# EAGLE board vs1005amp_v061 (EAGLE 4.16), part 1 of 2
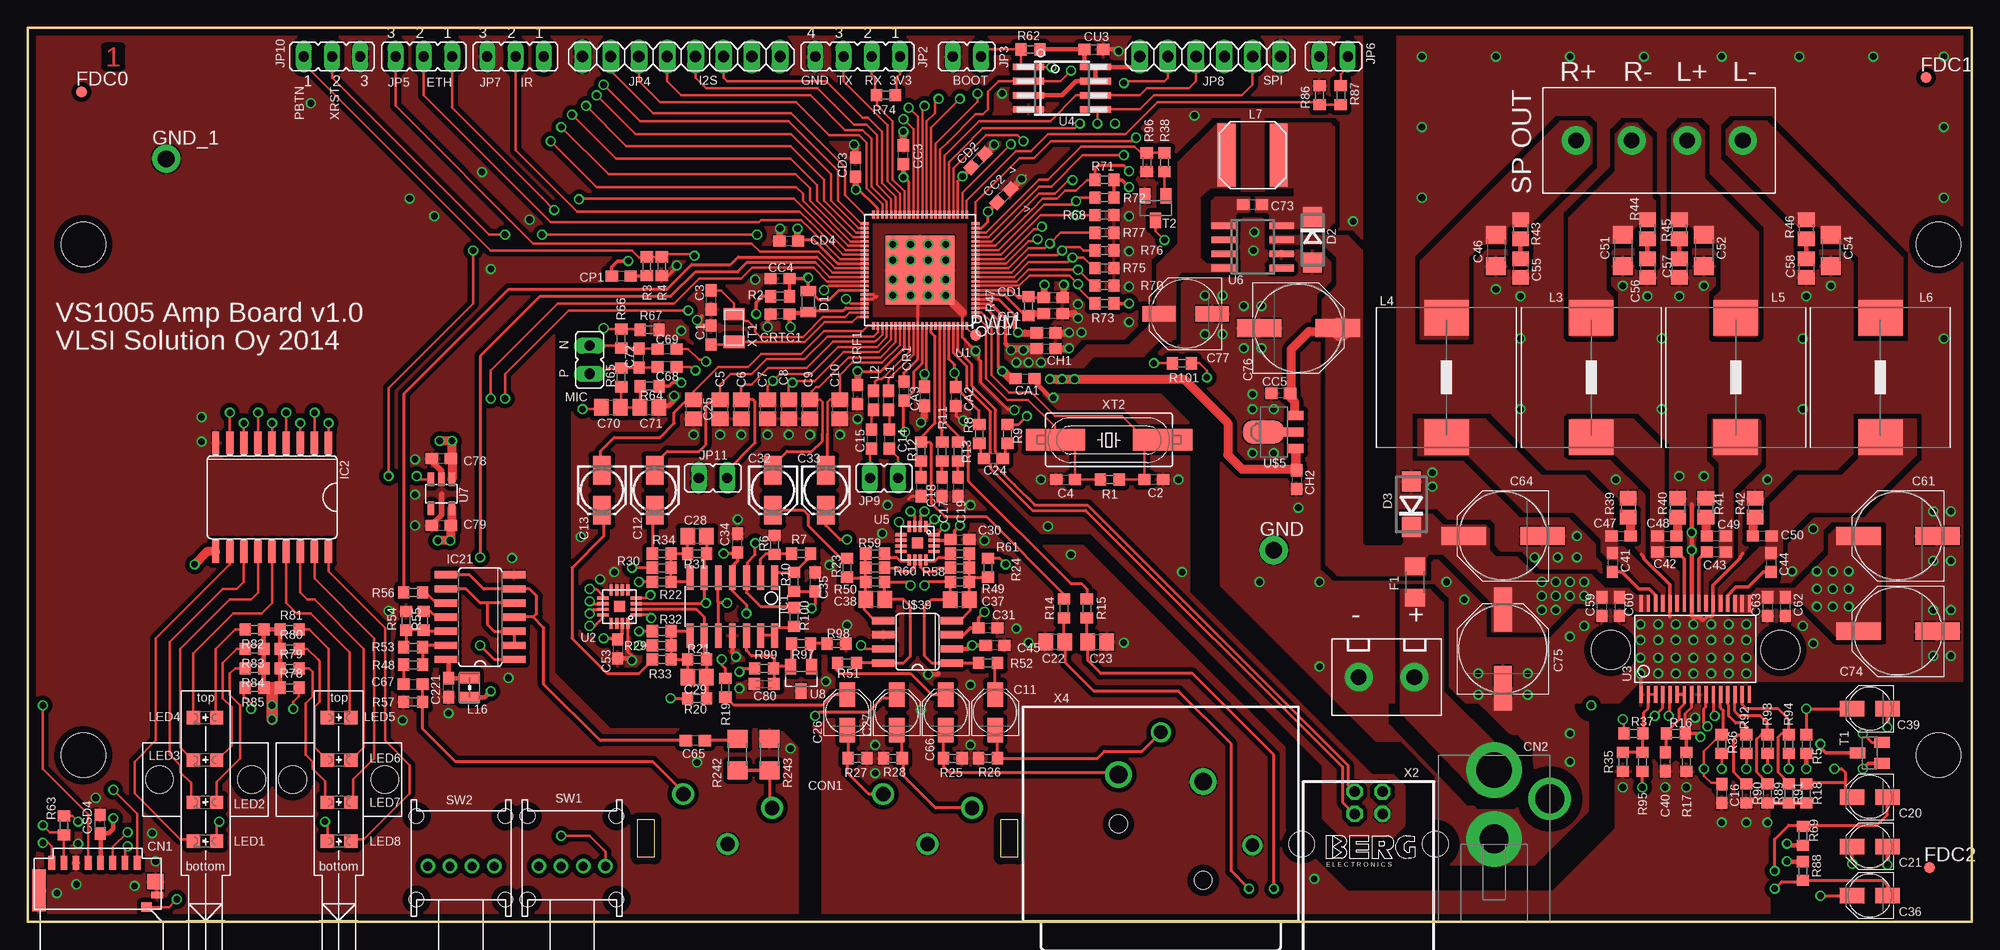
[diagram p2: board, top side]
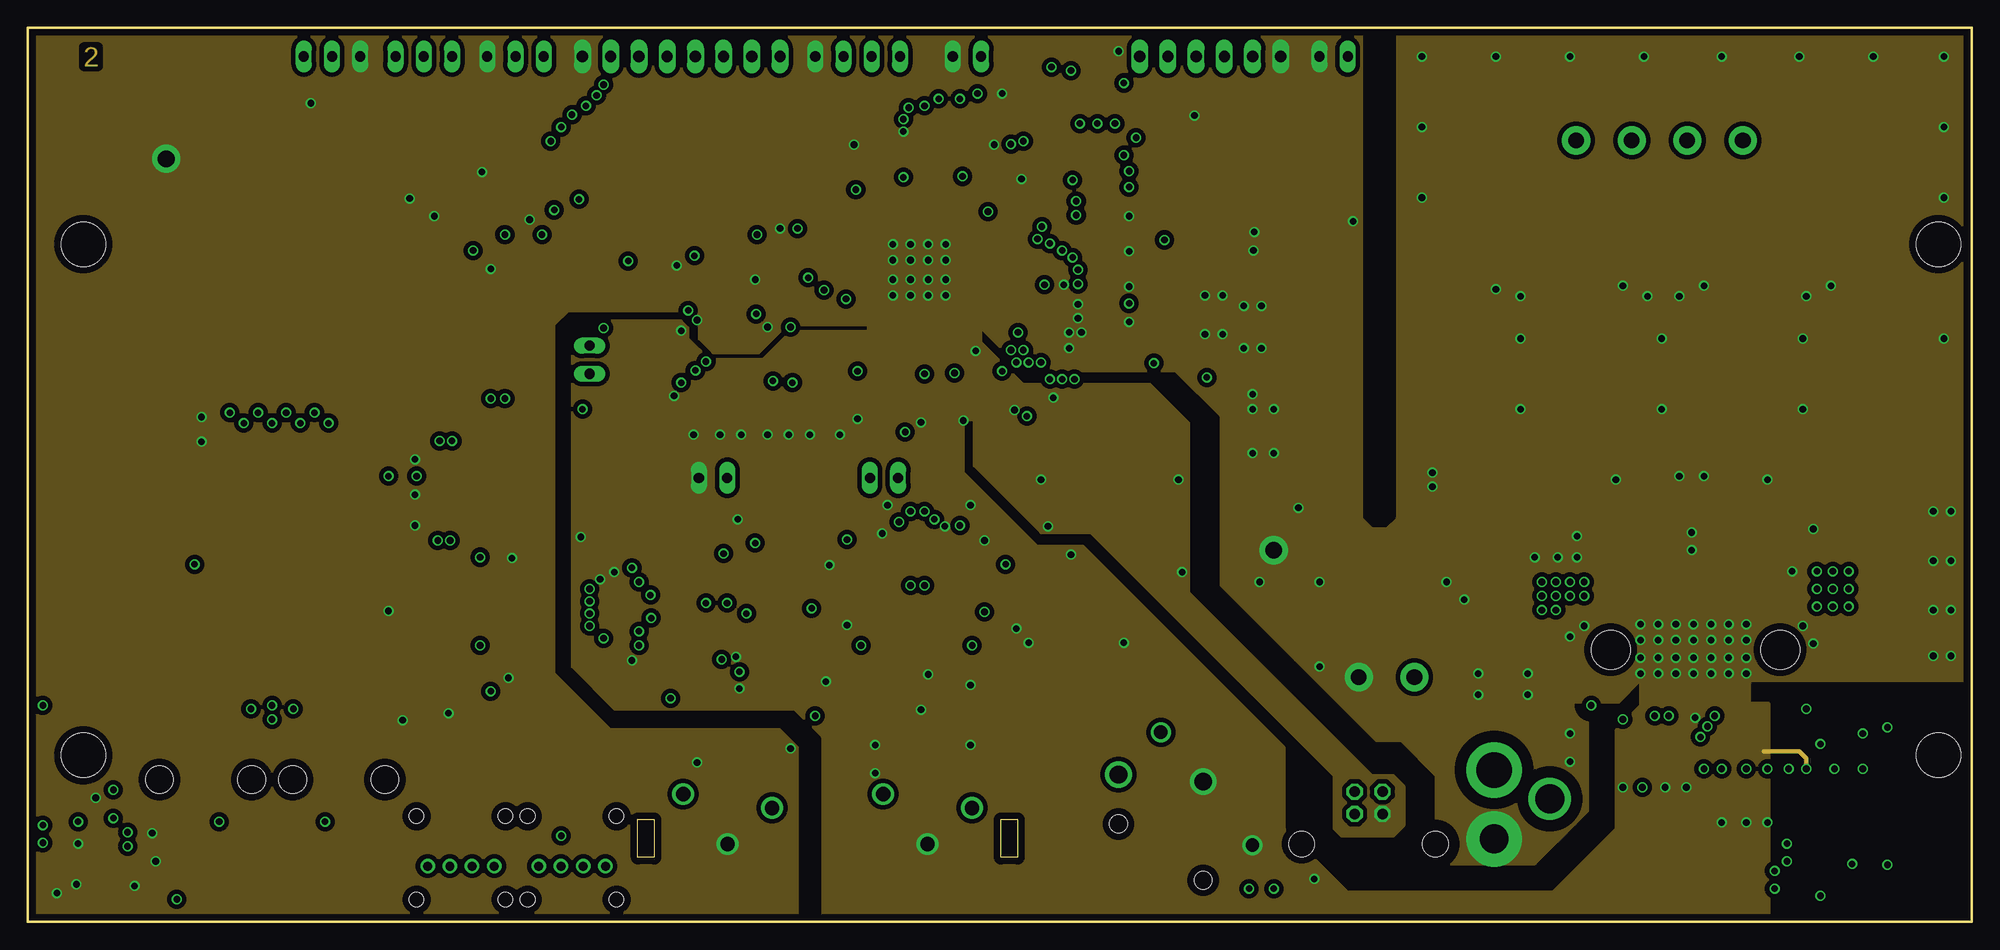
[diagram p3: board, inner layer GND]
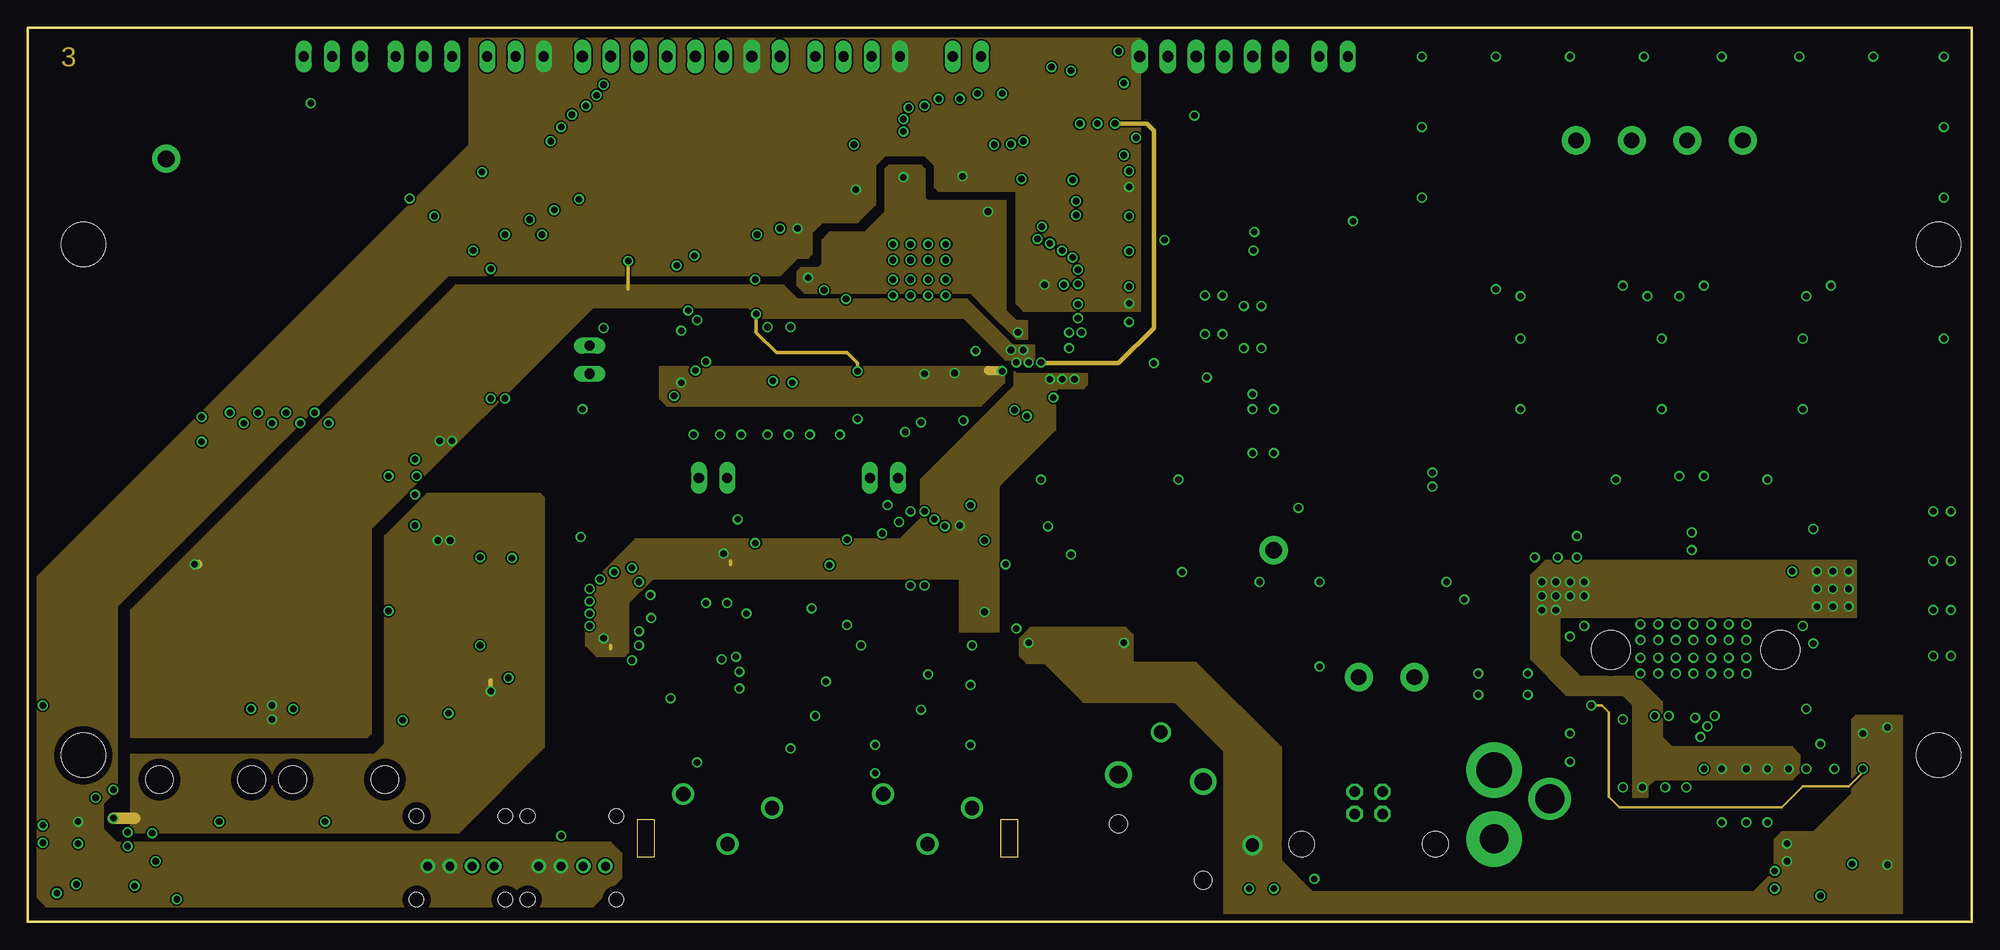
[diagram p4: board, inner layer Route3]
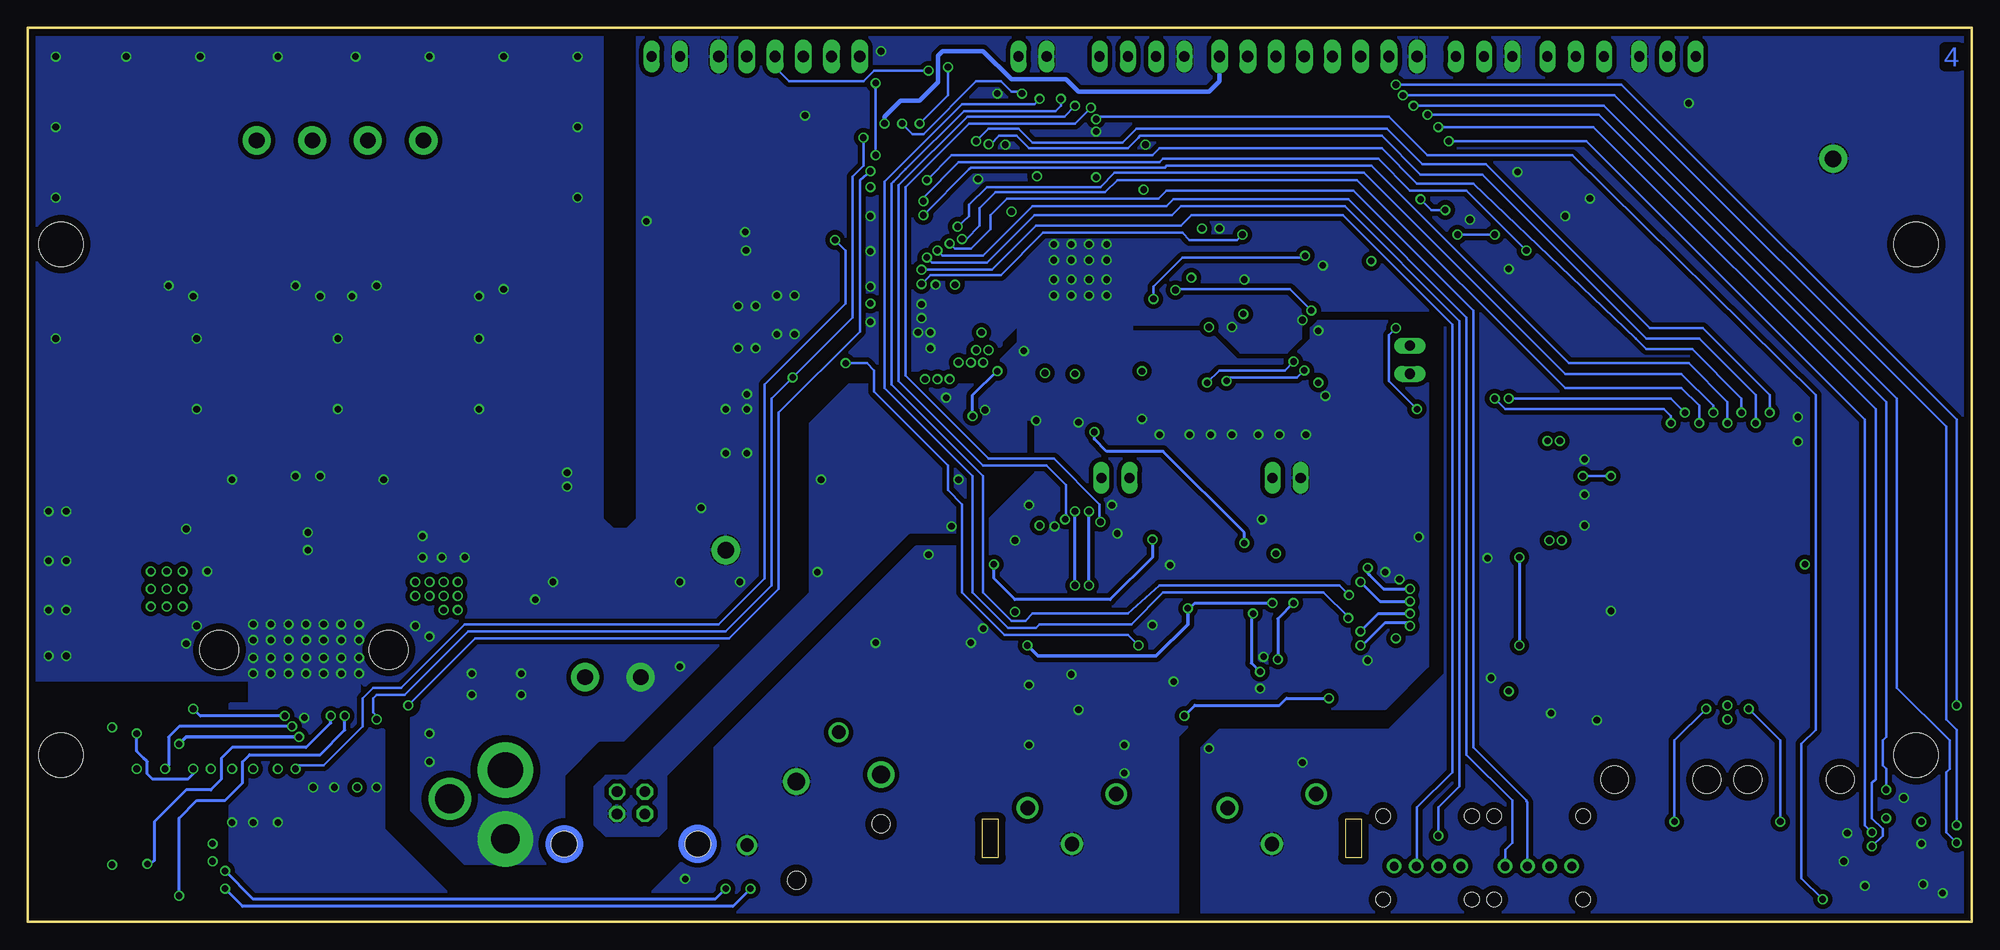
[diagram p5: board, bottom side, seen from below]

Size 175 x 80.5 mm. Coordinates in mm from the lower left corner, seen from the top.
Outline: 0,0 175,0 175,80.5 0,80.5 0,0
Copper layers (1*2+3*16): Top 0.0356mm / dielectric 0.2007mm / GND 0.0356mm / dielectric 0.2007mm / Route3 0.0356mm / dielectric 0.2007mm / Bottom 0.0356mm
Design rules "oma_4layer": minimum track width 8mil, minimum drill 0.3mm, track to track 5.5mil, track to pad 5.5mil, pad to pad 5.5mil, via to via 8mil, smd to smd 5mil, copper to edge 24mil, drill to drill 8mil, minimum pad ring 10mil, minimum via ring 0.15mm, stop-mask expansion 0.1mm, vias tented up to drill 100mil, thermal gap 5mil
Holes 4 mm at 172,15 5,15 172,61 5,61
Holes 3.5 mm at 157.75,24.5 142.5,24.5

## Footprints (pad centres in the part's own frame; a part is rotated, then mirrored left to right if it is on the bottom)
C0603 = smd 1.1 x 1: 1 -0.85,0; 2 0.85,0
C0805 = smd 1.3 x 1.5: 1 -0.85,0; 2 0.85,0
PANASONIC_B = smd 2.2 x 1.4: + 1.6,0; - -1.6,0
153CLV-0405 = smd 2.6 x 1.6: + 1.8,0; - -1.8,0
C1206 = smd 1.6 x 1.8: 1 -1.4,0; 2 1.4,0
PANASONIC_F = smd 4 x 1.6: + 3.55,0; - -3.55,0
PANASONIC_D = smd 3 x 1.4: + 2.4,0; - -2.4,0
C0603K = smd 1.05 x 1.08: 1 -0.875,0; 2 0.875,0
MSSN09-A0-300 = smd 0.6 x 1.25: 1 3.85,0; 2 2.75,0; 3 1.65,0; 4 0.55,0; 5 -0.55,0; 6 -1.65,0; 7 -2.75,0; 8 -3.85,0 | smd 1.2 x 3.79: 9 -5,-2.5 | smd 1.45 x 1.4: 10 5.5,-1.7 | smd 1.1 x 0.6: 11 5.65,-2.9 | smd 0.95 x 0.85: 12 4.7,-4
DC-JACK = drill 3.2 pad 5 round: 1 -13.7,0 | drill 2.6 pad 3.81 round: 2 -11.1,5 | drill 2.6 pad 5 round: 3 -7.5,0
LIGHT_PIPE4 = hole 2.5: -4.15,0; 4.15,0
4XRCA_2X2 = drill 1.3 round: GL 9,0; GR -9,0; RL 5,-3.25; RR -13,-3.25; WL 13,-4.5; WR -5,-4.5
MICROMELF-W = smd 0.9 x 1.4: A 0.95,0; C -0.95,0
DO214AC = smd 1.8 x 1.7: A 2.05,0; C -2.05,0
DO214BA = smd 1.8 x 1.7: A 2.05,0; C -2.05,0
R1206 = smd 1.6 x 1.803: 1 -1.422,0; 2 1.422,0
TP10R = smd 1 x 1: TP 0,0
MEAS_PIN = drill 1.5 pad 2.54 round: P$1 0,0
SO14 = smd 0.61 x 2.21: 1 -3.81,-2.603; 2 -2.54,-2.603; 3 -1.27,-2.603; 4 0,-2.603; 5 1.27,-2.603; 6 2.54,-2.603; 7 3.81,-2.603; 8 3.81,2.603; 9 2.54,2.603; 10 1.27,2.603; 11 0,2.603; 12 -1.27,2.603; 13 -2.54,2.603; 14 -3.81,2.603
SO18L = smd 0.66 x 2.032: 1 -5.08,-4.902; 2 -3.81,-4.902; 3 -2.54,-4.902; 4 -1.27,-4.902; 5 0,-4.902; 6 1.27,-4.902; 7 2.54,-4.902; 8 3.81,-4.902; 9 5.08,-4.902; 10 5.08,4.902; 11 3.81,4.902; 12 2.54,4.902; 13 1.27,4.902; 14 0,4.902; 15 -1.27,4.902; 16 -2.54,4.902; 17 -3.81,4.902; 18 -5.08,4.902
SO14' = smd 0.66 x 2.032: 1 -3.81,-3.073; 2 -2.54,-3.073; 3 -1.27,-3.073; 4 0,-3.073; 5 1.27,-3.073; 6 2.54,-3.073; 7 3.81,-3.073; 8 3.81,3.073; 9 2.54,3.073; 10 1.27,3.073; 11 0,3.073; 12 -1.27,3.073; 13 -2.54,3.073; 14 -3.81,3.073
JP4 = drill 0.914 long: 1 -3.81,0; 2 -1.27,0; 3 1.27,0; 4 3.81,0
JP1 = drill 0.914 long: 1 0,-1.27; 2 0,1.27
1X08 = drill 1.016 long: 1 -8.89,0; 2 -6.35,0; 3 -3.81,0; 4 -1.27,0; 5 1.27,0; 6 3.81,0; 7 6.35,0; 8 8.89,0
JP2 = drill 0.914 long: 1 -2.54,0; 2 0,0; 3 2.54,0
1X06 = drill 1.016 long: 1 -6.35,0; 2 -3.81,0; 3 -1.27,0; 4 1.27,0; 5 3.81,0; 6 6.35,0
0603 = smd 1.1 x 1: 1 -0.85,0; 2 0.85,0
RLF12560 = smd 3.2 x 4: 1 -5.375,0; 2 5.375,0
L_NR6045 = smd 1.6 x 5.7: 1 -2.35,0; 2 2.35,0
WE-KI_0805_B = smd 1.02 x 1.78: 1 -0.89,0; 2 0.89,0
CHIPLED_0805 = smd 1.2 x 1.2: A 0,-1.05; C 0,1.05
R0603 = smd 1 x 1.1: 1 -0.85,0; 2 0.85,0
R0805 = smd 1.3 x 1.5: 1 -0.85,0; 2 0.85,0
SW_MJTP2205D = drill 0.8 round: 1 3,0; 2 1,0; 3 -1,0; 4 -3,0 | hole 1.3: 4,-3; -4,-3; 4,4.5; -4,4.5
SOT23 = smd 1 x 1.4: 1 -0.95,-1.1; 2 0.95,-1.1; 3 0,1.1
QFN88_2 = smd 0.25 x 0.7: 1 0.8,0; 2 1.2,0; 3 1.6,0; 4 2,0; 5 2.4,0; 6 2.8,0; 7 3.2,0; 8 3.6,0; 9 4,0; 10 4.4,0; 11 4.8,0; 12 5.2,0; 13 5.6,0; 14 6,0; 15 6.4,0; 16 6.8,0; 17 7.2,0; 18 7.6,0; 19 8,0; 20 8.4,0; 21 8.8,0; 22 9.2,0; 45 9.2,10; 46 8.8,10; 47 8.4,10; 48 8,10; 49 7.6,10; 50 7.2,10; 51 6.8,10; 52 6.4,10; 53 6,10; 54 5.6,10; 55 5.2,10; 56 4.8,10; 57 4.4,10; 58 4,10; 59 3.6,10; 60 3.2,10; 61 2.8,10; 62 2.4,10; 63 2,10; 64 1.6,10; 65 1.2,10; 66 0.8,10 | smd 0.7 x 0.25: 23 10,0.8; 24 10,1.2; 25 10,1.6; 26 10,2; 27 10,2.4; 28 10,2.8; 29 10,3.2; 30 10,3.6; 31 10,4; 32 10,4.4; 33 10,4.8; 34 10,5.2; 35 10,5.6; 36 10,6; 37 10,6.4; 38 10,6.8; 39 10,7.2; 40 10,7.6; 41 10,8; 42 10,8.4; 43 10,8.8; 44 10,9.2; 67 0,9.2; 68 0,8.8; 69 0,8.4; 70 0,8; 71 0,7.6; 72 0,7.2; 73 0,6.8; 74 0,6.4; 75 0,6; 76 0,5.6; 77 0,5.2; 78 0,4.8; 79 0,4.4; 80 0,4; 81 0,3.6; 82 0,3.2; 83 0,2.8; 84 0,2.4; 85 0,2; 86 0,1.6; 87 0,1.2; 88 0,0.8 | smd 6.2 x 6.2: GNDPAD 5,5
QFN16 = smd 1 x 0.3: 1 -1.5,0.75; 2 -1.5,0.25; 3 -1.5,-0.25; 4 -1.5,-0.75; 9 1.5,-0.75; 10 1.5,-0.25; 11 1.5,0.25; 12 1.5,0.75 | smd 0.3 x 1: 5 -0.75,-1.5; 6 -0.25,-1.5; 7 0.25,-1.5; 8 0.75,-1.5; 13 0.75,1.5; 14 0.25,1.5; 15 -0.25,1.5; 16 -0.75,1.5 | smd 1 x 1: P$17 0,0
HTSSOP32 = smd 0.3 x 1.5: 1 -4.875,-4.1; 2 -4.225,-4.1; 3 -3.575,-4.1; 4 -2.925,-4.1; 5 -2.275,-4.1; 6 -1.625,-4.1; 7 -0.975,-4.1; 8 -0.325,-4.1; 9 0.325,-4.1; 10 0.975,-4.1; 11 1.625,-4.1; 12 2.275,-4.1; 13 2.925,-4.1; 14 3.575,-4.1; 15 4.225,-4.1; 16 4.875,-4.1; 17 4.875,4.1; 18 4.225,4.1; 19 3.575,4.1; 20 2.925,4.1; 21 2.275,4.1; 22 1.625,4.1; 23 0.975,4.1; 24 0.325,4.1; 25 -0.325,4.1; 26 -0.975,4.1; 27 -1.625,4.1; 28 -2.275,4.1; 29 -2.925,4.1; 30 -3.575,4.1; 31 -4.225,4.1; 32 -4.875,4.1
SO-8MN = smd 0.6 x 2.8: 1 -1.905,-3.013; 2 -0.635,-3.013; 3 0.635,-3.013; 4 1.905,-3.013; 5 1.905,3.013; 6 0.635,3.013; 7 -0.635,3.013; 8 -1.905,3.013
SO08 = smd 0.6 x 2.2: 1 -1.905,-2.6; 2 -0.635,-2.6; 3 0.635,-2.6; 4 1.905,-2.6; 5 1.905,2.6; 6 0.635,2.6; 7 -0.635,2.6; 8 -1.905,2.6
SOT23-5L = smd 0.55 x 1.2: 1 -0.95,-1.3; 2 0,-1.3; 3 0.95,-1.3; 4 0.95,1.3; 5 -0.95,1.3
SOT23@1 = smd 1 x 1.4: 1 -0.95,-1.1; 2 0.95,-1.1; 3 0,1.1
SOT89 = smd 0.8 x 1.4: 1 -1.499,-1.981; 3 1.499,-1.981 | smd 2.032 x 3.65: 2 0,0.94 | smd 0.8 x 1.9: 2@1 0,-1.727
SO08' = smd 0.66 x 2.032: 1 -1.905,-3.073; 2 -0.635,-3.073; 3 0.635,-3.073; 4 1.905,-3.073; 5 1.905,3.073; 6 0.635,3.073; 7 -0.635,3.073; 8 -1.905,3.073
TER_BLOCK-4-WAY = drill 1.4 pad 2.54 round: P$1 2.5,0; P$2 -2.5,0; P$3 -7.5,0; P$4 7.5,0
PN61729 = drill 0.95 octagon: 1 1.25,4.71; 2 -1.25,4.71; 3 -1.25,2.71; 4 1.25,2.71 | hole 2.3: -6.02,0; 6.02,0
TER_BLOCK-2-WAY = drill 1.4 pad 2.54 round: P$1 2.5,0; P$2 -2.5,0
NC3FAH2 = drill 1.6 round: 1 -3.81,0.635; 2 3.81,0 | drill 1.2 round: 3 0,-3.815; G -8.25,6.355 | hole 1.6: -3.81,9.525; 3.81,4.445
CRYSTAL_1206 = smd 1.1 x 1.9: 1 -1.25,0; 2 1.25,0
HC49UP = smd 5.334 x 1.93: 1 -4.826,0; 2 4.826,0

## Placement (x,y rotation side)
C1  18p  [C0603]  61.52,52.83 270 top
C2  30p  [C0603]  101.37,39.81 180 top
C3  18p  [C0603]  61.52,56 90 top
C4  30p  [C0603]  93.43,39.81 0 top
C5  10n/NPO  [C0805]  62.32,46.16 270 top
C6  10n/NPO  [C0805]  64.22,46.16 270 top
C7  10n/NPO  [C0805]  66.6,46.16 270 top
C8  10n/NPO  [C0805]  68.51,46.16 270 top
C9  10n/NPO  [C0805]  70.41,46.16 270 top
C10  10n/NPO  [C0805]  73.11,46.16 270 top
C11  10u  [PANASONIC_B]  87.08,18.86 90 top
C12  1u  [153CLV-0405]  56.44,38.86 270 top
C13  1u  [153CLV-0405]  51.68,38.86 270 top
C14  100p  [C0603]  77.56,43.46 270 top
C15  100p  [C0603]  75.97,43.46 270 top
C16  NC  [C0603]  152.49,11.55 270 top
C17  47n  [C0603]  82.32,39.17 270 top
C18  10n  [C0603]  80.41,39.17 270 top
C19  10n  [C0603]  83.75,39.17 270 top
C20  10u  [PANASONIC_B]  165.82,11.23 180 top
C21  10u  [PANASONIC_B]  165.82,6.79 180 top
C22  10n/NP0  [C0805]  92.48,25.2 180 top
C23  10n/NP0  [C0805]  96.29,25.2 0 top
C24  1p  [C0603]  86.92,41.72 0 top
C25  10n/NPO  [C0805]  59.94,46.16 270 top
C26  10u  [PANASONIC_B]  73.79,18.84 90 top
C27  10u  [PANASONIC_B]  78.23,18.84 90 top
C28  68p/NP0  [C0805]  60.25,34.73 180 top
C29  68p/NP0  [C0805]  60.25,22.03 180 top
C30  100n  [C0603]  83.91,34.41 0 top
C31  100n  [C0603]  86.45,26.48 0 top
C32  1u  [153CLV-0405]  67.08,38.86 270 top
C33  1u  [153CLV-0405]  71.84,38.86 270 top
C34  100n  [C0603]  63.91,34.09 90 top
C35  100n  [C0603]  70.89,30.6 90 top
C36  10u  [PANASONIC_B]  165.82,2.34 180 top
C37  68p/NP0  [C0805]  83.91,29.02 180 top
C38  68p/NP0  [C0805]  76.29,29.02 180 top
C39  10u  [PANASONIC_B]  165.82,19.17 180 top
C40  1u/16V X5R  [C0603]  147.41,14.41 270 top
C41  220n/25V X5R  [C0603]  142.64,32.35 270 top
C42  220n/25V X5R  [C0603]  147.57,33.3 0 top
C43  220n/25V X5R  [C0603]  152.01,33.3 180 top
C44  220n/25V X5R  [C0603]  156.93,32.35 270 top
C45  100n  [C0603]  87.08,24.89 180 top
C46  680n/50V  [C1206]  132.17,60.45 270 top
C47  330p/50V NP0  [C0603]  143.44,34.73 0 top
C48  330p/50V NP0  [C0603]  147.57,34.73 0 top
C49  330p/50V NP0  [C0603]  152.01,34.73 180 top
C50  330p/50V NP0  [C0603]  156.14,34.73 180 top
C51  680n/50V  [C1206]  143.6,60.45 270 top
C52  680n/50V  [C1206]  150.9,60.45 270 top
C53  100n  [C0603]  53.11,24.57 270 top
C54  680n/50V  [C1206]  162.33,60.45 270 top
C55  10n/50V NP0  [C0805]  134.39,58.86 270 top
C56  10n/50V NP0  [C0805]  145.82,58.86 270 top
C57  10n/50V NP0  [C0805]  148.68,58.86 270 top
C58  10n/50V NP0  [C0805]  160.11,58.86 270 top
C59  1nF/50V  [C0603]  141.69,28.38 270 top
C60  100n/50V  [C0603]  143.28,28.38 270 top
C61  220u/35V (EEE-FP1V221AP)  [PANASONIC_F]  168.36,34.73 180 top
C62  1n/50V  [C0603]  158.2,28.38 270 top
C63  100n/50V  [C0603]  156.62,28.38 270 top
C64  220u/35V (EEE-FP1V221AP)  [PANASONIC_F]  132.8,34.73 180 top
C65  100n  [C0603]  60.09,16.32 180 top
C66  10u  [PANASONIC_B]  82.64,18.86 90 top
C67  10n  [C0603]  34.7,21.39 0 top
C68  100n  [C0603]  57.55,49.97 180 top
C69  100n  [C0603]  57.55,51.56 180 top
C70  10u  [C0805]  52.48,46.32 0 top
C71  10u  [C0805]  55.97,46.32 0 top
C72  10p/NP0  [C0603]  55.02,50.76 90 top
C73  10n  [C0603]  110.26,64.58 0 top
C74  220u/35V (EEE-FP1V221AP)  [PANASONIC_F]  168.36,26.16 180 top
C75  220u/35V (EEE-FP1V221AP)  [PANASONIC_F]  132.8,24.57 90 top
C76  220u/35V (EEE-FP1V221AP)  [PANASONIC_F]  114.39,53.46 0 top
C77  100u/35V (EEE-FPV101XAP)  [PANASONIC_D]  104.23,54.73 180 top
C78  1u  [C0603]  37.23,41.72 180 top
C79  1u  [C0603]  37.23,35.68 180 top
C80  100p/NP0  [C0603K]  66.29,21.4 180 top
C221  100n  [C0603]  37.87,21.08 90 top
CA1  10u/6V3  [C0603]  89.77,48.9 0 top
CA2  10u/6V3  [C0603]  83.54,47.29 270 top
CA3  10u/6V3  [C0603]  80.72,47.31 270 top
CC1  1u  [C0603]  91.68,53.03 0 top
CC2  100n  [C0603]  87.87,65.36 45 top
CC3  100n  [C0603]  78.82,69.06 90 top
CC4  100n  [C0603]  67.72,57.91 180 top
CC5  100n  [C0603]  112.8,47.59 180 top
CD1  1u  [C0603]  92.31,56.2 0 top
CD2  100n  [C0603]  85.53,68.54 45 top
CD3  100n  [C0603]  74.53,67.95 90 top
CD4  100n  [C0603]  68.5,61.28 180 top
CF1  1u  [C0603]  92.31,54.78 0 top
CH1  10u/6V3  [C0603]  91.68,51.6 0 top
CH2  10u/6V3  [C0603]  114.23,39.81 270 top
CN1  CON-USD  [MSSN09-A0-300]  6,5.32 0 top
CN2  RAPC722X / PJ-102AH(5A/24V)  [DC-JACK]  132.01,-0.04 270 top
CN4  LIGHT_PIPE4  [LIGHT_PIPE4]  16,12.8 0 top
CN5  LIGHT_PIPE4  [LIGHT_PIPE4]  28,12.8 0 top
CON1  CON_RCA_2X2  [4XRCA_2X2]  72,7 180 top
CP1  100n  [C0603]  53.43,58.15 0 top
CR1  1uF  [C0603]  78.9,47.79 90 top
CRF1  10uF/6V3  [C0603]  74.69,47.47 270 top
CRTC1  10u/6V3  [C0603]  67.72,54.73 180 top
CSD4  10u/6V3  [C0603]  6.52,8.79 90 top
CU3  100n  [C0603]  95.97,78.55 0 top
D1  1N4148-U  [MICROMELF-W]  70.25,55.84 90 top
D2  SS14  [DO214AC]  115.66,61.4 270 top
D3  S10M-TP  [DO214BA]  124.55,37.59 90 top
F1  0440005.WR(5A/32V)  [R1206]  124.87,30.6 90 top
FDC0  PTR1TP10R  [TP10R]  4.85,74.73 0 top
FDC1  PTR1TP10R  [TP10R]  170.9,76 0 top
FDC2  PTR1TP10R  [TP10R]  171.22,4.89 0 top
GND  [MEAS_PIN]  112.16,33.46 0 top
GND_1  [MEAS_PIN]  12.47,68.7 0 top
IC1  OPA1654AID  [SO14]  63.43,28.38 180 top
IC2  [SO18L]  21.99,38.22 180 top
IC21  SN74AC04D  [SO14']  40.73,27.43 90 top
JP2  RS232  [JP4]  74.7,77.91 180 top
JP3  [JP1]  84.54,77.91 90 top
JP4  [1X08]  58.83,77.91 180 top
JP5  [JP2]  35.65,77.91 180 top
JP6  TRIG_IN 12V  [JP1]  117.56,77.91 90 top
JP7  [JP2]  43.9,77.91 180 top
JP8  [1X06]  106.45,77.91 0 top
JP9  FM_ANT  [JP1]  77.08,39.97 90 top
JP10  [JP2]  27.39,77.91 0 top
JP11  AD  [JP1]  61.68,39.97 270 top
L1  120nH  [0603]  77.48,46.95 270 top
L2  120nH  [0603]  76.13,46.95 270 top
L3  RLF12560T-100M7R5  [RLF12560]  140.74,49.02 90 top
L4  RLF12560T-100M7R5  [RLF12560]  127.72,49.02 90 top
L5  RLF12560T-100M7R5  [RLF12560]  153.76,49.02 90 top
L6  RLF12560T-100M7R5  [RLF12560]  166.78,49.02 90 top
L7  NR6045T680M  [L_NR6045]  110.26,69.02 180 top
L16  BLM21P221SG  [WE-KI_0805_B]  39.77,21.08 90 top
LED1  KP-2012QBC-D  [CHIPLED_0805]  15.96,7.27 90 top
LED2  KP-2012QBC-D  [CHIPLED_0805]  15.96,10.76 90 top
LED3  KP-2012QBC-D  [CHIPLED_0805]  15.96,14.57 90 top
LED4  KP-2012QBC-D  [CHIPLED_0805]  15.96,18.38 90 top
LED5  KP-2012QBC-D  [CHIPLED_0805]  28.03,18.38 270 top
LED6  KP-2012QBC-D  [CHIPLED_0805]  28.03,14.57 270 top
LED7  KP-2012QBC-D  [CHIPLED_0805]  28.03,10.76 270 top
LED8  KP-2012QBC-D  [CHIPLED_0805]  28.03,7.27 270 top
MIC  [JP1]  50.57,50.61 180 top
PWM  PTR1TP10R  [TP10R]  85.34,52.83 0 top
R1  1M  [R0603]  97.4,39.81 180 top
R2  51R  [R0603]  67.72,56.32 0 top
R3  100K  [R0603]  55.73,59.02 90 top
R4  200K  [R0603]  57.08,59.02 270 top
R5  NC  [R0603]  160.11,16 270 top
R6  10k  [R0603]  67.24,33.94 90 top
R7  4.7k  [R0603]  69.62,33.14 0 top
R8  1M  [R0603]  85.65,43.94 90 top
R9  1M  [R0603]  88.19,43.94 90 top
R10  1k  [R0603]  68.98,30.6 270 top
R11  10R  [R0603]  82.32,42.35 90 top
R12  20R  [R0603]  80.41,42.35 90 top
R13  20R  [R0603]  83.75,42.35 90 top
R14  220R  [R0603]  93.27,28.22 90 top
R15  220R  [R0603]  95.34,28.22 90 top
R16  100k  [R0603]  148.36,16.95 0 top
R17  20k  [R0603]  149.31,14.41 270 top
R18  NC  [R0603]  160.11,11.55 270 top
R19  47k  [R0603]  62.79,21.08 270 top
R20  47k  [R0603]  60.25,20.12 180 top
R21  39k  [R0603]  60.25,23.62 0 top
R22  39k  [R0603]  57.08,30.6 180 top
R23  220R  [R0603]  73.75,31.87 90 top
R24  220R  [R0603]  86.45,31.87 90 top
R25  100k  [R0603]  83.27,14.73 180 top
R26  100k  [R0603]  86.45,14.73 0 top
R27  100k  [R0603]  74.7,14.73 180 top
R28  100k  [R0603]  77.88,14.73 0 top
R29  39k  [R0603]  57.08,24.89 180 top
R30  16.9k  [R0603]  57.08,31.87 180 top
R31  39k  [R0603]  60.25,33.14 0 top
R32  16.9k  [R0603]  57.08,26.16 180 top
R33  220R  [R0603]  57.08,23.62 180 top
R34  220R  [R0603]  57.08,33.14 180 top
R35  100K  [R0603]  143.6,14.41 90 top
R36  10K  [R0603]  152.49,16 270 top
R37  1K  [R0603]  144.55,16.95 180 top
R38  10K  [R0603]  102.32,68.38 270 top
R39  10R  [R0805]  144.07,37.27 90 top
R40  10R  [R0805]  148.52,37.27 90 top
R41  10R  [R0805]  151.06,37.27 90 top
R42  10R  [R0805]  155.5,37.27 90 top
R43  3.3R  [R0805]  134.39,62.35 270 top
R44  3.3R  [R0805]  145.82,62.35 270 top
R45  3.3R  [R0805]  148.68,62.35 270 top
R46  3.3R  [R0805]  160.11,62.35 270 top
R47  10R  [R0603]  90.1,55.45 270 top
R48  100R  [R0603]  34.7,23.14 180 top
R49  30k  [R0603]  83.91,30.6 0 top
R50  30k  [R0603]  76.29,30.6 180 top
R51  47k  [R0603]  73.75,23.3 0 top
R52  47k  [R0603]  86.45,23.3 180 top
R53  10K  [R0603]  34.7,24.73 0 top
R54  10K  [R0603]  34.06,27.11 90 top
R55  10R  [R0603]  35.65,27.11 90 top
R56  10R  [R0603]  34.7,29.65 180 top
R57  75R  [R0603]  34.7,19.81 180 top
R58  30k  [R0603]  83.91,31.87 180 top
R59  30k  [R0603]  76.29,33.14 0 top
R60  14.7k  [R0603]  76.29,31.87 0 top
R61  14.7k  [R0603]  83.91,33.14 180 top
R62  100K  [R0603]  90.26,78.55 180 top
R63  4K7  [R0603]  3.26,8.7 90 top
R64  1K  [R0603]  55.97,48.22 180 top
R65  1K  [R0603]  53.43,49.02 90 top
R66  1k  [R0603]  53.43,52.51 90 top
R67  1K  [R0603]  55.97,53.3 0 top
R68  100K  [R0603]  96.92,63.62 180 top
R69  10k  [R0603]  159.79,7.74 270 top
R70  100K  [R0603]  96.92,57.27 0 top
R71  100K  [R0603]  96.92,66.8 180 top
R72  100K  [R0603]  96.92,65.21 180 top
R73  100K  [R0603]  96.92,55.69 180 top
R74  100K  [R0603]  77.24,74.42 180 top
R75  100K  [R0603]  96.92,58.86 0 top
R76  100K  [R0603]  96.92,60.45 0 top
R77  100K  [R0603]  96.92,62.03 0 top
R78  1K  [R0603]  23.58,21.08 0 top
R79  1K  [R0603]  23.58,22.82 0 top
R80  1K  [R0603]  23.58,24.57 0 top
R81  1K  [R0603]  23.58,26.32 0 top
R82  1K  [R0603]  20.41,26.32 180 top
R83  1K  [R0603]  20.41,24.57 180 top
R84  1K  [R0603]  20.41,22.82 180 top
R85  1K  [R0603]  20.41,21.08 180 top
R86  10K  [R0603]  116.29,74.42 90 top
R87  27K  [R0603]  118.2,74.42 90 top
R88  10k  [R0603]  159.79,4.57 90 top
R89  0R  [R0603]  156.62,11.55 270 top
R90  0R  [R0603]  154.71,11.55 270 top
R91  0R  [R0603]  158.52,11.55 270 top
R92  NC  [R0603]  154.71,16 90 top
R93  NC  [R0603]  156.62,16 90 top
R94  NC  [R0603]  158.52,16 90 top
R95  NC  [R0603]  145.34,14.41 270 top
R96  10K  [R0603]  100.73,68.38 90 top
R97  10k  [R0603]  69.62,25.05 180 top
R98  3k  [R0603]  72.8,25.05 180 top
R99  4.7k  [R0603]  66.29,22.82 180 top
R100  NC  [R0603]  68.98,27.43 90 top
R101  1K  [R0603]  103.91,50.29 180 top
R242  249  [R1206]  63.91,15.05 90 top
R243  107  [R1206]  66.76,15.05 90 top
SW1  SW_MJTP2205D  [SW_MJTP2205D]  49,5 0 top
SW2  SW_MJTP2205D  [SW_MJTP2205D]  39,5 0 top
T1  SI2302ADS  [SOT23]  165.82,15.2 90 top
T2  BC848  [SOT23]  101.53,64.26 180 top
U1  VS1005  [QFN88_2]  85.33,53.66 90 top
U2  ISL54405IRTZ  [QFN16]  53.27,28.38 180 top
U3  TPA3116D2  [HTSSOP32]  150.11,24.57 0 top
U4  25LCXXXXSOM  [SO-8MN]  93.11,75.05 270 top
U5  ISL54405IRTZ  [QFN16]  80.1,34.09 270 top
U6  LM2675MX-5.0  [SO08]  110.26,60.77 270 top
U7  ZXCL330E5TA  [SOT23-5L]  37.23,38.54 180 top
U8  LM4041CIDBZTG4  [SOT23@1]  69.62,21.87 180 top
U$5  MC78L05ACHX  [SOT89]  112.16,44.1 90 top
U$39  OPA1632  [SO08']  80.1,25.2 90 top
X1  1935187  [TER_BLOCK-4-WAY]  146.89,70.35 0 top
X2  61729-0010BLF  [PN61729]  120.7,7 0 top
X3  1935161  [TER_BLOCK-2-WAY]  122.33,22.03 0 top
X4  NC3FAAH2-0  [NC3FAH2]  102,13.25 180 top
XT1  32.768kHz/12p  [CRYSTAL_1206]  63.59,53.46 270 top
XT2  12.288MHz/18p  [HC49UP]  97.34,43.39 0 top

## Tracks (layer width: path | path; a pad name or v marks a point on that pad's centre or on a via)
1
  pour Top (isolate 1.016, no thermals): 123.59,18.86 130.58,11.55 131.22,11.55 131.53,11.23 132.8,11.23 133.36,11.71 133.99,12.35 133.99,12.82 134.39,13.22 134.39,14.41 133.12,15.68 132.49,15.68 127.41,20.76 127.41,28.7 126.21,29.89 123.59,29.89
3V3  (via drill 0.6)
  Top 0.406: CSD4.1 6.44,8.06 6.55,7.95 | 6.55,7.95 CN1.4 | L16.1 41.11,20.19 v41.68,20.76 | 6.55,7.95 7.28,7.95 7.71,8.38 v7.71,9.33
  Top 0.508: 38.19,34.41 38.11,34.41 v38.03,34.33
  Top 0.813: 38.19,35.69 38.09,35.78 C79.1 38.09,34.47 38.03,34.41 v38.03,34.33 v36.92,34.33 | 38.19,35.69 U7.5 | 38.19,35.69 38.19,35.68
  Route3 0.406: 41.68,21.71 v41.68,20.76
  Route3 1.016: 9.61,9.33 v7.71,9.33
  pour Route3 (no thermals): 35.97,38.54 32.16,34.73 32.16,16 31.2,15.05 9.3,15.05 9.3,8.06 38.82,8.06 46.44,15.68 46.44,38.22 46.12,38.54
12M
  Top 0.203: U1.44 75.33,63.66 73.58,65.41 73.58,67.95 68.7,72.83 56.28,72.83 52.48,76.64 JP4.7
+5V  (via drill 0.6)
  Top 0.254: R99.2 64.38,22.82 v64.06,22.51 | IC1.4 63.43,29.81 64.7,28.54 v64.7,27.74
  Top 0.305: 53.11,25.52 C53.1 | U2.15 53.52,25.93 53.11,25.52 | 53.11,25.52 v51.84,25.52 | C34.1 63.91,33.14 | IC1.4 63.43,32.03 63.91,32.51 63.91,33.14 | 63.91,33.14 v62.63,33.14 | U$39.3 84.22,25.84 84.86,26.48 C31.1 85.6,27.37 v86.13,27.9 | U5.15 82.89,34.34 82.95,34.41 C30.1 83.11,34.41 83.43,34.73 83.43,35.21 v83.91,35.68
  Top 0.813: v92,48.86 92.64,48.86 92.69,48.8 92.96,48.8 92.96,48.86 v93.11,48.86 v94.23,48.86 104.07,48.86 108.04,44.89 108.04,42.03 109.31,40.76 114.07,40.76 114.15,40.84 U$5.1 114.15,41 114.39,40.76 114.28,40.66 CH2.1
  Route3 0.305: 52.48,24.57 52.48,24.89 | 63.27,32.19 63.27,32.51 | v86.13,27.9 86.45,28.06 | v83.91,35.68 84.07,35.68
  Bottom 0.254: v64.06,22.51 | v64.06,22.51 64.86,23.3 64.86,27.59 v64.7,27.74
  pour Route3 (no thermals): 88.83,48.22 88.35,47.75 88.35,47.75 80.41,39.81 80.41,36.32 78.51,34.41 54.7,34.41 50.25,29.97 50.25,24.89 51.2,23.94 53.74,23.94 54.06,24.25 54.06,28.7 56.28,30.92 83.91,30.92 83.91,26.16 87.4,26.16 87.4,39.17 92.48,44.26 92.48,47.75 92.8,48.06 95.02,48.06 95.34,48.38 95.34,49.34 88.99,49.34 88.83,49.49
AUX2
  Top 0.203: U1.69 76.93,52.88 76.44,52.39 76.28,52.24 72.47,52.24 70.09,49.85 66.65,49.85 65.17,48.38 64.54,48.38 64.22,48.06 64.22,47.11 | 64.22,47.11 64.22,47.43 | C6.1 64.22,47.11
  Top 0.254: C6.1 65.28,47.01 65.49,46.8 65.49,43.14 62.95,40.6 JP11.2 62.95,39.81
AVDD  (via drill 0.6)
  Top 0.203: R64.1 57.24,48.22
  Top 0.254: U1.3 86.27,55.26 87.39,54.14 87.39,50.01 | U1.79 80.93,49.42 80.79,49.28 80.72,49.22 | CA3.1 80.72,47.95 | 80.72,49.22 | U1.84 82.93,50.67 83.43,50.16 v83.43,49.41 | 83.74,48.11 | v83.43,49.41 | 83.59,48.09 CA2.1 83.54,48.11 85.65,46 R8.2 | v83.43,49.41 83.59,49.26 83.59,48.09 | R9.2 89.2,44.79 v89.94,45.52 | 83.74,48.11 83.63,48.11 83.59,48.06 83.59,48.09
  Top 0.305: v87.72,49.57 | 87.39,50.01 87.39,49.9 v87.72,49.57 | 57.24,48.22 57.71,48.22 58.03,48.54 v58.83,48.54
  Top 0.406: 80.79,49.28 v80.73,49.34 | v80.73,49.34 | v80.73,49.34
  Top 0.61: CA3.1 80.72,49.22 | 88.98,48.9 CA1.1 88.5,48.9
  Top 0.813: v87.72,49.57 87.8,49.57 88.47,48.9 88.5,48.9
  Route3 0.305: v58.83,48.54 59.14,48.7
  Route3 0.813: 86.45,49.65 87.72,49.65 | 86.45,49.65
  Bottom 0.254: v89.94,45.52 89.94,47.43 87.72,49.65
  Bottom 0.406: 87.72,49.65 | 87.72,49.65 v87.72,49.57
  pour Route3 (no thermals): 56.92,49.97 56.92,47.11 57.55,46.48 85.81,46.48 87.88,48.54 87.88,49.81 87.72,49.97 87.4,49.97
AVDDRF  (via drill 0.6)
  Top 0.203: CRF1.1 74.69,48.58 74.69,48.59 74.69,48.74
  Top 0.254: U1.74 78.93,51.71 76.76,49.54 74.69,49.54
  Top 0.305: v65.57,54.73 65.57,55.76 66.13,56.32 R2.1
  Top 0.406: 74.7,49.49 | v74.7,49.57 74.7,49.49 | 74.69,49.54 74.69,49.5 74.7,49.49
  Top 0.61: 74.69,49.54 74.69,48.74 | 74.69,48.74
  Route3 0.305: v65.57,54.73 65.57,53.07 67.4,51.24 73.75,51.24 74.7,50.29 74.7,49.65 | 74.7,49.65 | 74.7,49.65 v74.7,49.57
BCK
  Top 0.203: U1.41 77.33,64.84 75.96,66.21 75.96,70.17 75.96,70.49 75.17,71.29 73.58,71.29 70.45,74.42 58.83,74.42 57.55,75.69 JP4.5
CMD  (via drill 0.6)
  Top 0.203: U1.50 73.84,60.86 69.77,64.94 69.77,65.57 69.18,66.16 51.2,66.16 v47.08,70.29 | CN1.3 7.65,6.73 v8.98,8.06
  Bottom 0.203: v47.08,70.29 34.7,70.29 9.61,45.21 9.61,8.7 v8.98,8.06
CVDD  (via drill 0.6)
  Top 0.203: 78.82,67.16 78.82,67.12 v78.83,67.04 | U1.5 85.4,56.06 85.42,56.08
  Top 0.254: U1.5 87.37,56.06 88.82,54.62 | CC1.1 90.89,53.03 | U1.36 79.33,66.65 78.82,67.16 | CC3.1 78.82,68.43 | U1.21 85.87,62.46 86.44,63.03 86.44,63.85 86.52,63.94 | 89.14,53.03 | 89.14,53.03 | U1.60 73.02,56.86 72.16,56 71.21,56 70.41,56.8 70.41,56.79 D1.A | 86.52,63.94 86.52,64.01 | 86.52,63.94 86.53,63.94 v86.45,63.94
  Top 0.305: D1.A v70.25,57.99 70.18,57.91 CC4.1 68.56,56.42 68.59,56.4 68.56,56.38 R2.2 | 88.82,54.62 88.82,53.47 89.15,53.14 v89.15,53.07 89.07,53.07 | 89.07,53.07 89.1,53.03 89.14,53.03 | 89.07,53.07 88.99,53.14
  Top 0.406: 78.82,67.16 CC3.1 | 87.31,64.8 86.52,64.01 87.31,64.8 | 87.31,64.8 | 87.31,64.8 CC2.1
  Top 0.61: 89.77,53.03 | 89.77,53.03 CC1.1 | 89.77,53.03 | 89.14,53.03 89.77,53.03 | 89.77,53.03
  pour Route3 (no thermals): 88.99,52.51 89.94,52.51 89.94,54.1 88.99,54.1 88.03,55.05 88.03,64.89 81.05,64.89 80.73,65.21 80.73,67.75 80.41,68.07 77.56,68.07 77.24,67.75 77.24,63.94 75.34,62.03 72.16,62.03 71.53,61.4 71.53,59.18 71.21,58.86 69.62,58.86 69.3,58.54 69.3,57.27 69.94,56.64 84.86,56.64 86.45,55.05
DI
  Top 0.203: U1.39 78.13,65.31 76.91,66.52 76.91,71.13 75.64,72.4 75.17,72.4 71.88,75.69 62.95,75.69 62.63,76 JP4.3
DO
  Top 0.203: U1.40 77.73,65.07 76.44,66.36 76.44,70.81 75.49,71.76 74.38,71.76 72.63,73.51 71.08,75.05 61.05,75.05 60.09,76 JP4.4
E-RXP  (via drill 0.6)
  Top 0.203: U1.51 73.61,60.46 68.98,65.09 49.73,65.09 v49.62,65.05 | JP5.1 38.19,73.31 46.28,65.21 v47.39,64.1
  Bottom 0.203: v47.39,64.1 48.66,64.1 v49.62,65.05
E-TXN
  Top 0.203: U1.55 72.67,58.86 71.2,60.33 65.93,60.33 65.17,61.08 45.49,61.08 33.11,73.47 JP5.3
E-TXP
  Top 0.203: U1.53 73.14,59.66 70.41,62.4 69.61,63.19 66.01,63.19 65.81,62.99 47.08,62.99 35.65,74.42 JP5.2
FRM
  Top 0.203: U1.42 76.93,64.6 75.49,66.05 75.49,70.17 74.85,70.81 72.15,70.81 69.18,73.78 56.92,73.78 55.02,75.69 JP4.6
FVDD
  Top 0.203: 90.1,54.57 | R47.2 90.1,54.57 | 89.93,54.78 89.93,54.74 90.1,54.57
  Top 0.254: CF1.1 91.52,54.78 | U1.6 87.77,56.46 | 87.77,56.46 | 87.77,56.46 87.89,56.46 89.76,54.6 R47.2
  Top 0.61: CF1.1 91.04,54.78 89.93,54.78
GAIN  (via drill 0.6)
  Top 0.203: U1.17 87.13,60.86 89.77,63.51 90.41,64.14 | 90.41,64.14 91.36,65.09 92.63,65.09 93.38,65.84 94.38,65.84 95.34,66.8 R71.2 | 90.41,64.14
  Top 0.254: R71.2 96.08,67.85 96.29,68.07 98.67,68.07 v99.15,67.59
  Top 0.305: T1.1 165.67,14.25 v165.19,13.77
  Route3 0.203: v165.19,13.77 165.19,13.46 163.92,12.19 159.79,12.19 157.88,10.28 143.28,10.28 142.33,11.23 142.33,18.86 141.69,19.49 v140.74,19.49
  Bottom 0.203: v99.15,67.59 100.1,66.8 100.1,53.14 107.4,45.84 107.4,29.97 111.85,25.52 134.71,25.52 v140.74,19.49
GBUF
  Top 0.254: U1.82 82.13,44.45 82.32,44.26 R11.2
GND  (via drill 0.6)
  Top 0.203: U1.GNDPAD 80.33,58.74 80.25,58.74 81.04,56.2 | 81.04,56.2 | 89.19,66.57 89.14,66.52 | 89.19,66.57 89.19,66.59 89.19,66.6 v89.46,66.88 | 89.19,66.57 89.82,67.2 | 76.13,56.16 76.37,56.24 76.45,56.32 | CN1.10 11.52,3.62 11.65,3.48 CN1.11 | 86.96,69.89 86.96,69.93 v87,69.97
  Top 0.254: 84.13,54.86 U1.87 84.13,52.61 v85.34,51.4 85.65,51.08 85.65,50.61 85.81,50.45 85.81,48.54 88.19,46.16 88.83,46.16 | CR1.2 78.9,49.46 80.13,50.69 U1.77 80.13,56.2 81.04,56.2 | 76.37,56.24 | U1.61 76.14,56.46 76.29,56.32 | 76.29,56.32 76.37,56.24 | U1.62 76.03,56.06 76.29,56.32 | CA2.2 83.59,46.39 83.59,45.52 83.91,45.21 84.22,45.21 v84.22,45.13 | v84.22,45.13 | C18.2 79.56,38.33 79.3,38.06 | U2.16 54.02,24.3 54.38,23.94 v54.38,23.54 | v82.56,35.6 | U5.16 81.8,34.84 v82.56,35.6 | U3.22 151.73,29.3 151.69,29.33 | 147.8,28.62 147.83,28.64 U3.28 | U3.25 149.78,28.55 149.79,28.54 | T1.2 165.98,16.15 v165.19,16.95
  Top 0.305: 145.26,33.06 145.5,32.83 145.5,32.67 147.8,30.36 147.8,28.62 147.8,27.43 | 154.39,33.14 154.15,32.9 154.15,32.75 151.69,30.29 151.69,29.33 151.69,27.59 151.61,27.51 151.22,27.51 150.9,27.19 | U3.1 145.23,22.3 v145.19,22.35 | v58.43,59.1 58.43,58.94 57.66,58.17 R4.2
  Top 0.406: v81.05,22.27 81.92,22.27 82,22.35 | 90.85,48.9 90.73,49.02 | v92.32,47.19 92.32,47.11 92.16,47.11 91.05,48.22 | 149.79,28.7 149.79,33.3 | v149.79,35.05 149.79,34.65 | v149.79,35.05 149.79,37.59 | 149.79,28.62 149.79,28.54 149.79,27.59 149.95,27.43 150.5,27.43 150.74,27.19 | v149.79,33.46 v149.79,35.05 | v54.38,23.54 54.38,23.62 54.28,23.72 C53.2 | v58.19,47.35 58.19,46.95 57.71,46.48 57.24,46.48 56.82,46.06 | 56.82,46.06 56.68,45.92 | 56.82,46.06 C71.2 | v66.6,53.54 66.6,54.73 | v98.19,78.39 | CU3.2 98.04,78.55 v98.19,78.39 | 167.41,17.59 | v167.41,17.51 167.41,17.59 | C39.- 167.42,17.6 167.41,17.59 | v158.36,7.03 158.36,6.95 158.42,6.89 R69.2 | v158.36,5.44 158.36,5.36 158.42,5.42 R88.2 | v167.41,5.12 167.41,5.2 167.42,5.21 C21.- | v160.11,13.77 R5.2 | R18.2 158.62,10.7 158.52,10.6 R91.2 156.72,10.7 156.62,10.6 R89.2 | 60.25,54.1 v60.25,54.18 | 60.25,54.1 60.65,54.49 | 60.25,54.1 60.25,53.86 60.41,53.7 61.52,53.7 C1.1 | CA1.2 90.62,48.65 91.05,48.22 | 91.05,48.22 | v63.75,23.86 63.75,23.94 63.43,24.25 IC1.11
  Top 0.508: 37.23,40.45 37.23,40.6 36.68,41.16 | 36.68,41.16 | 36.68,41.16 36.52,41.32 36.52,41.72 | 37.23,38.54 37.23,36.63 36.28,35.68
  Top 0.61: CC2.2 88.5,65.92 89.19,66.59 | 80.72,45.41 CA3.2 | CC3.2 78.82,71.13 | 86.96,69.89 86.3,69.22 86.28,69.22 86.21,69.21 CD2.2 | CD3.2 74.53,69.86 | CD4.2 67.71,61.44 67.71,62.4 | CA1.2 90.85,48.9 | 93.74,53.03 93.58,53.03 CC1.2 | CC1.2 | 94.22,54.78 | CF1.2 94.22,54.78 | 93.27,57.32 93.27,56.36 CD1.2 | CH1.2 93.58,51.6
  Top 0.813: 84.13,54.86 81.04,57.95
  GND 0.406: v160.11,13.77 160.11,14.73 159.47,15.36 156.3,15.36
  Bottom 0.254: v165.19,16.95 165.19,15.36 164.55,14.73 | 164.55,14.73 | 164.39,14.57 164.55,14.73 | 164.39,14.57 | 164.39,14.57 164.24,14.41 164.24,13.3 163.76,12.82 160.58,12.82 160.11,13.3 v160.11,13.77
  other vias: 77.88,61 79.46,61 81.05,61 82.64,61 82.64,59.57 82.64,57.83 82.64,56.4 81.05,56.4 79.46,56.4 77.88,56.4 77.88,57.83 77.88,59.57 79.46,57.83 81.05,57.83 81.05,59.57 79.46,59.57 74.7,45.29 93.75,53.07 93.75,51.64 93.27,57.35 65.49,57.83 67.72,62.43 74.38,69.97 78.83,71.16 94.54,55.61 94.54,54.34 87.72,74.58 73.11,43.86 70.41,43.86 68.51,43.86 66.6,43.86 64.22,43.86 62.32,43.86 59.94,43.86 80.42,44.97 77.4,37.51 84.86,37.51 88.83,46.08 86.13,34.33 88.99,26.4 84.86,15.92 76.29,15.92 76.29,13.38 84.86,21.32 80.42,19.09 73.75,26.71 76.92,34.97 72.16,32.11 51.52,30.84 52.79,31.48 63.91,36.24 156.62,8.93 154.71,8.93 37.87,18.78 43.59,32.75 32.47,27.98 91.21,39.81 103.59,39.81 68.67,15.6 58.83,53.22 148.68,40.13 150.9,40.13 156.62,39.81 154.71,26.79 154.71,25.36 154.71,23.78 154.71,22.35 145.19,26.79 145.19,25.36 145.19,23.78 146.77,26.79 146.77,25.36 146.77,23.78 146.77,22.35 148.36,26.79 148.36,25.36 148.36,23.78 148.36,22.35 149.95,26.79 149.95,25.36 149.95,23.78 149.95,22.35 151.53,26.79 151.53,25.36 151.53,23.78 151.53,22.35 153.12,26.79 153.12,25.36 153.12,23.78 153.12,22.35 140.11,26.63 138.83,25.68 159.79,26.63 160.74,25.05 160.74,35.36 158.84,31.55 139.47,34.73 135.66,32.82 137.72,32.82 139.47,32.82 173.12,32.51 171.54,32.51 171.54,36.95 173.12,36.95 171.54,28.06 173.12,28.06 173.12,23.93 171.54,23.93 135.03,22.35 135.03,20.44 130.58,20.44 130.58,22.35 142.96,39.81 126.45,40.44 126.45,39.17 132.17,56.95 134.39,56.32 143.6,57.27 145.82,56.32 148.68,56.32 150.9,57.27 160.11,56.32 162.33,57.27 111.05,55.45 105.97,56.4 110.42,62.11 150.11,18.38 152.49,8.93 149.31,12.11 147.41,12.11 107.56,56.4 109.47,55.45 105.97,52.91 107.56,52.91 109.47,51.64 111.05,51.64 99.15,63.54 99.15,60.37 99.15,57.19 94.86,53.07 105.02,72.59 119.31,63.07 143.6,12.11 49.78,34.65 93.91,33.06 98.67,25.13 90.1,25.13 115.82,3.85 60.25,14.33 172.49,77.91 166.14,77.91 159.47,77.91 152.49,77.91 145.5,77.91 138.83,77.91 132.17,77.91 125.5,77.91 125.5,71.56 172.49,71.56 172.49,65.21 125.5,65.21 172.49,52.51 159.79,46.16 147.09,46.16 134.39,46.16 134.39,52.51 147.09,52.51 159.79,52.51 116.29,22.98 110.9,30.6 116.29,30.6 11.52,5.44 4.37,3.38 2.63,2.58 9.61,3.22 11.2,7.98 33.74,18.14 6.12,11.16 25.49,73.7 34.38,65.13 36.6,63.54 41.68,58.78 34.85,35.68 34.85,41.64 34.85,38.46 15.65,45.45 15.65,43.22 43.27,21.95 4.53,7.03 99.15,54.02 91.85,35.6 103.91,31.48 127.72,30.6 129.31,29.01 110.34,60.45 138.83,14.41 138.83,16.95 40.89,67.51 45.17,63.23 64.06,21 71.84,21.63 114.39,37.27 110.26,46.16 112.16,46.16 112.16,42.19 110.26,42.19 110.26,47.51
  pour Top (isolate 0.406, rank 2): 0.09,80.47 0.09,0.12 69.3,0.12 69.3,15.68 67.72,17.27 52.48,17.27 47.39,22.35 47.39,53.78 48.66,55.05 59.46,55.05 60.41,54.1 60.41,52.51 61.68,51.24 65.81,51.24 68.35,53.78 75.65,53.78 75.65,53.14 68.67,53.14 66.13,50.61 61.37,50.61 59.46,52.51 59.46,53.46 58.83,54.1 49.94,54.1 48.98,53.14 48.98,22.98 52.79,19.17 68.98,19.17 71.53,16.63 71.53,0.12 156.77,-0.04 156.77,19.65 155.03,19.65 155.03,21.39 145.19,21.39 145.19,19.49 142.96,17.27 142.96,8.38 137.25,2.66 118.83,2.66 113.12,8.38 113.12,15.68 95.02,33.78 90.89,33.78 84.22,40.45 84.22,45.21 85.18,45.21 85.18,41.08 91.21,35.05 95.66,35.05 116.61,14.09 116.61,9.33 118.2,7.74 122.96,7.74 123.91,8.7 123.91,12.19 122.96,13.14 121.06,13.14 104.55,29.65 104.55,44.89 102,47.43 90.58,47.43 85.81,52.19 85.81,54.1 84.54,55.37 84.54,56.32 87.4,53.46 87.4,51.88 89.62,49.65 103.28,49.65 107.4,45.52 107.4,30.29 117.88,19.81 143.28,19.81 145.19,21.71 175.03,21.71 175.08,21.81 174.92,80.61 123.28,80.61 123.28,36.32 122.33,35.37 121.06,35.37 120.1,36.32 120.1,80.47
  pour Top: 145.5,23.3 145.5,16.95 154.71,16.95 154.71,23.3
  pour Top (isolate 1.016, rank 2, no thermals): 142.33,20.12 123.91,20.12 122.33,21.71 122.33,22.98 121.69,23.62 114.07,23.62 121.37,16.32 123.59,16.32 126.77,13.14 126.77,5.84 127.41,5.2 135.66,5.2 140.42,9.96 140.42,18.22
  pour GND (isolate 0.406, rank 2, no thermals): 0.09,80.47 0.09,0.12 69.3,0.12 69.3,15.68 67.72,17.27 52.48,17.27 47.39,22.35 47.39,53.78 48.66,55.05 59.46,55.05 60.41,54.1 60.41,52.51 61.68,51.24 65.81,51.24 68.35,53.78 75.65,53.78 75.65,53.14 68.67,53.14 66.13,50.61 61.37,50.61 59.46,52.51 59.46,53.46 58.83,54.1 49.94,54.1 48.98,53.14 48.98,22.98 52.79,19.17 68.98,19.17 71.53,16.63 71.53,0.12 156.77,-0.04 156.77,19.65 155.03,19.65 155.03,21.55 145.19,21.55 145.19,19.49 142.96,17.27 142.96,8.38 137.25,2.66 118.83,2.66 113.12,8.38 113.12,15.68 95.02,33.78 90.89,33.78 84.22,40.45 84.22,45.21 85.18,45.21 85.18,41.08 91.21,35.05 95.66,35.05 117.56,13.14 117.56,8.38 118.2,7.74 122.96,7.74 123.91,8.7 123.91,12.19 122.96,13.14 121.06,13.14 104.55,29.65 104.55,44.89 101.05,48.38 89.62,48.38 85.81,52.19 85.81,53.46 89.62,49.65 103.28,49.65 107.4,45.52 107.4,30.29 117.88,19.81 143.28,19.81 145.19,21.71 175.03,21.71 175.08,21.81 174.92,80.61 123.28,80.61 123.28,36.32 122.33,35.37 121.06,35.37 120.1,36.32 120.1,80.47
  pour GND (isolate 1.016, rank 2, no thermals): 142.33,20.12 123.91,20.12 122.33,21.71 122.33,22.98 121.69,23.62 114.07,23.62 121.37,16.32 123.59,16.32 126.77,13.14 126.77,5.84 127.41,5.2 135.66,5.2 140.42,9.96 140.42,18.22
  pour Bottom (isolate 0.406, rank 2): 0.09,80.47 0.09,0.12 69.3,0.12 69.3,15.68 67.72,17.27 52.48,17.27 47.39,22.35 47.39,53.78 48.66,55.05 59.46,55.05 60.41,54.1 60.41,52.51 61.68,51.24 65.81,51.24 68.35,53.78 75.65,53.78 75.65,53.14 68.67,53.14 66.13,50.61 61.37,50.61 59.46,52.51 59.46,53.46 58.83,54.1 49.94,54.1 48.98,53.14 48.98,22.98 52.79,19.17 68.98,19.17 71.53,16.63 71.53,0.12 156.77,-0.04 156.77,19.65 155.03,19.65 155.03,21.55 145.19,21.55 145.19,19.49 142.96,17.27 142.96,8.38 137.25,2.66 118.83,2.66 113.12,8.38 113.12,15.68 95.02,33.78 90.89,33.78 84.22,40.45 84.22,45.21 85.18,45.21 85.18,41.08 91.21,35.05 95.66,35.05 117.56,13.14 117.56,8.38 118.2,7.74 122.96,7.74 123.91,8.7 123.91,12.19 122.96,13.14 121.06,13.14 104.55,29.65 104.55,44.89 101.05,48.38 89.62,48.38 85.81,52.19 85.81,53.78 87.4,52.19 87.4,51.88 89.62,49.65 103.28,49.65 107.4,45.52 107.4,30.29 117.88,19.81 143.28,19.81 145.19,21.71 175.03,21.71 175.08,21.81 174.92,80.61 123.28,80.61 123.28,36.32 122.33,35.37 121.06,35.37 120.1,36.32 120.1,80.47
  pour Bottom (isolate 0.61, rank 2, no thermals): 142.33,20.12 123.91,20.12 122.33,21.71 122.33,22.98 121.69,23.62 114.07,23.62 121.37,16.32 123.59,16.32 126.77,13.14 126.77,5.84 127.41,5.2 135.66,5.2 140.42,9.96 140.42,18.22
  pour Route3 (no thermals): 164.24,18.22 164.24,11.55 160.74,8.06 157.88,8.06 157.25,7.43 157.25,4.57 155.34,2.66 115.66,2.66 112.8,5.52 112.8,15.68 105.18,23.3 99.47,23.3 99.47,25.84 98.83,26.48 90.26,26.48 89.31,25.52 89.31,23.94 89.94,23.3 91.53,23.3 95.02,19.81 103.28,19.81 107.72,15.36 107.72,0.12 168.68,0.12 168.68,18.54 164.55,18.54
GPIO0_0  (via drill 0.6)
  Top 0.203: U1.9 89.01,57.66 90.09,58.74 94.5,58.74 v94.54,58.7 95.97,57.27 R70.1
  Bottom 0.203: v94.54,58.7 88.19,58.7 84.22,62.67 71.21,62.67 70.25,63.62 56.6,63.62 46.76,53.78 46.76,13.46 49.94,10.28 49.94,5.2 50,5.14 SW1.2 | v94.54,58.7 | v94.54,58.7 | v94.54,58.7 | v94.54,58.7 94.7,58.54
GPIO0_1  (via drill 0.6)
  Top 0.203: U1.10 88.78,58.06 90.09,59.38 93.63,59.38 v94.07,59.81 95.02,59.81 95.97,58.86 R75.1 | v48.03,7.74 50.57,7.74 51.84,6.47 52,6.31 52,5.12 52.08,5.04 52.03,5 SW1.1
  Bottom 0.203: v94.07,59.81 93.59,59.34 88.67,59.34 84.38,63.62 72,63.62 71.21,64.42 56.44,64.42 46.12,54.1 46.12,12.19 48.03,10.28 v48.03,7.74
GPIO0_2  (via drill 0.6)
  Top 0.203: U1.11 88.54,58.46 90.09,60.01 92.68,60.01 v93.11,60.45 93.43,60.77 94.7,60.77 95.02,60.45 R76.1
  Bottom 0.203: v93.11,60.45 92.64,59.97 88.99,59.97 84.54,64.42 72.48,64.42 71.84,65.05 56.13,65.05 45.49,54.41 45.49,15.05 41.36,10.92 41.36,7.11 42,6.47 42,5.2 SW2.1
GPIO0_3  (via drill 0.6)
  Top 0.203: U1.12 88.31,58.86 90.09,60.65 91.57,60.65 v92,61.08 92.96,62.03 R77.1
  Bottom 0.203: v92,61.08 91.53,60.61 90.1,60.61 88.35,62.35 88.35,63.62 86.84,65.13 73.19,65.13 72.48,65.84 55.65,65.84 44.86,55.05 44.86,15.68 40.09,10.92 40.09,10.84 40.01,10.76 40.01,5.04 40.06,5 | 40.06,5 40.09,4.96 | 40.06,5 SW2.2
GPIO0_4  (via drill 0.6)
  Top 0.203: U1.13 88.07,59.26 90.09,61.28 90.7,61.28 v90.89,61.48 | v24.53,44.89 IC2.3
  Bottom 0.203: v90.89,61.48 90.5,61.48 89.31,62.67 89.31,64.26 87.88,65.69 78.03,65.69 76.92,66.8 55.33,66.8 36.6,48.06 26.12,48.06 24.53,46.48 v24.53,44.89
GPIO0_5  (via drill 0.6)
  Top 0.203: U1.14 87.89,59.66 90.58,62.35 91.05,62.35 v91.29,62.59 | v23.27,45.84 IC2.4
  Bottom 0.203: v91.29,62.59 90.26,63.54 90.26,64.58 88.67,66.16 78.43,66.16 77.16,67.43 54.7,67.43 36.6,49.34 26.12,49.34 23.27,46.48 v23.27,45.84
GPIO0_6  (via drill 0.6)
  Top 0.203: U1.15 87.6,60.06 91.16,63.62 v94.38,63.62 R68.2 | v21.99,44.89 IC2.5
  Bottom 0.203: 90.26,67.75 v94.38,63.62 | 90.26,67.75 | 90.26,67.75 90.1,67.91 72.64,67.91 72.48,68.07 54.06,68.07 36.28,50.29 25.49,50.29 21.99,46.8 v21.99,44.89
GPIO0_9  (via drill 0.6)
  Top 0.203: U1.18 86.74,61.26 91.04,65.57 92.47,65.57 93.7,66.8 v94.07,66.8 | v20.73,45.84 IC2.6
  Bottom 0.203: v94.07,66.8 91.84,69.02 73.75,69.02 73.11,69.66 53.11,69.66 49.94,66.48 44.86,66.48 30.25,52.51 29.3,51.56 25.17,51.56 20.73,47.11 v20.73,45.84
GPIO0_10  (via drill 0.6)
  Top 0.203: U1.24 84.13,65.64 v88.5,70.02 | v19.45,44.89 IC2.7
  Bottom 0.203: v88.5,70.02 88.31,70.02 87.56,70.77 85.97,70.77 84.86,69.66 75.97,69.66 75.02,70.61 | 75.02,70.61 | 75.02,70.61 74.86,70.77 53.11,70.77 49.62,67.27 44.06,67.27 29.3,52.51 24.53,52.51 19.45,47.43 v19.45,44.89
GPIO0_11  (via drill 0.6)
  Top 0.203: U1.26 83.33,67.86 86.28,70.81 89.1,70.81 v89.62,70.29 | v18.19,45.84 IC2.8
  Bottom 0.203: v89.62,70.29 | v89.62,70.29 88.51,71.4 85.81,71.4 84.54,70.13 76.45,70.13 75.18,71.4 52.63,71.4 49.46,68.23 43.74,68.23 28.98,53.46 24.22,53.46 18.19,47.43 v18.19,45.84
GPIO0_14  (via drill 0.6)
  Top 0.203: U1.58 71.96,57.66 70.72,58.9 65.22,58.9 64.22,57.91 60.41,57.91 58.19,55.69 47.71,55.69 41.68,49.65 v41.68,47.11 | v25.8,45.84 IC2.2
  Bottom 0.203: v41.68,47.11 27.08,47.11 v25.8,45.84
GPIO0_15  (via drill 0.6)
  Top 0.203: v59.46,55.05 48.66,55.05 42.95,49.34 v42.95,47.11 | v27.08,44.89 IC2.1
  Top 0.254: U1.59 72.09,57.26 v71.68,56.88
  Bottom 0.203: 71.6,56.95 61.37,56.95 v59.46,55.05 | v27.08,44.89 27.08,45.52 27.71,46.16 42,46.16 v42.95,47.11
  Bottom 0.254: 71.6,56.95 v71.68,56.88
INSENS1_RCA  (via drill 0.6)
  Top 0.203: U1.31 81.33,71.52 v83.91,74.1
  Top 0.254: U2.1 55.77,27.63 v56.13,27.35
  Bottom 0.203: v83.91,74.1 84.38,73.62 90.89,73.62 97.88,66.64 97.88,48.06 89.94,40.13 89.94,29.65 86.77,26.48 84.22,26.48 83.91,26.79 75.65,26.79 72.8,29.65 58.35,29.65 56.13,27.43 v56.13,27.35
INSENS1_XLR  (via drill 0.6)
  Top 0.203: U1.33 80.53,73.26 v80.73,73.47
  Top 0.254: U5.1 80.96,35.59 v81.61,36.24
  Bottom 0.203: v80.73,73.47 81.69,72.51 90.42,72.51 96.61,66.32 96.61,48.7 88.99,41.08 83.27,41.08 81.53,39.33 81.53,36.63
  Bottom 0.254: v81.61,36.24 81.53,36.63
INSENS2_RCA  (via drill 0.6)
  Top 0.203: 80.93,70.85 U1.32 80.93,72.07 81.69,72.83 81.69,73.78 v82,74.1 | v56.05,29.41 55.81,29.17 54.7,29.17 54.74,29.13 U2.4
  Bottom 0.203: v82,74.1 82,73.47 82.48,72.99 90.73,72.99 95.97,67.75 97.08,66.64 | 97.08,66.64 | 97.08,66.64 97.24,66.48 97.24,48.38 88.99,40.13 88.99,29.65 86.45,27.11 85.18,27.11 84.54,27.74 75.97,27.74 73.11,30.29 56.92,30.29 v56.05,29.41
INSENS2_XLR  (via drill 0.6)
  Top 0.203: U5.4 78.91,35.59 78.51,36 v78.43,36 | U1.34 80.13,72.48 v79.3,73.31
  Bottom 0.203: v79.3,73.31 80.73,71.88 90.26,71.88 95.97,66.16 95.97,49.18 88.51,41.72 82.64,41.72 78.51,37.59 78.51,36 v78.43,36
IOVDD  (via drill 0.6)
  Top 0.203: CD2.1 84.97,67.98 | 84.86,67.87 84.97,67.98 | 84.97,67.98 | 91.52,57.32 91.52,57.27 91.53,57.27 v91.53,57.35 | JP2.1 78.51,76.32 78.19,76 78.19,74.42 R74.1 | 90.1,56.32 | 90.1,56.32 R47.1 | 89.14,56.2 89.98,56.2 90.1,56.32 | R63.2 4,9.55 v4.53,9.01 | 74.53,66.08 74.54,66.08 v74.54,65.92 | 84.21,67.13 84.22,67.11 | 84.22,67.11 v84.15,67.11 | 84.22,67.11
  Top 0.254: U1.25 83.73,66.69 84.83,67.79 84.85,67.79 84.86,67.89 84.86,67.87 | 84.97,67.98 CD2.1 84.86,67.87 | U1.43 76.53,64.21 74.53,66.21 74.53,67 CD3.1 | 69.3,61.44 70.72,61.44 72.9,59.26 U1.54 | U1.7 88.48,56.86 89.14,56.2 CD1.1 91.68,56.2
  Top 0.305: v69.3,62.43 69.3,62.35 69.3,62.36 69.3,62.4 | R72.1 97.78,66.69 97.88,66.8 R71.1 98.51,66.8 v99.15,66.16 | R73.1 v99.15,55.69
  Top 0.406: 84.86,67.87 84.85,67.79 84.85,67.78 84.21,67.13 84.19,67.11 | U4.8 U4.7 94.38,75.69 93.11,74.42 U4.3 | JP8.1 100.1,77.59 99.47,76.96 96.29,76.96 | U4.8 95.97,76.96 | U4.8 96.29,76.96 | 96.29,76.96 95.34,76.96 95.12,77.17 CU3.1 R62.1
  Top 0.61: 84.86,67.87 | 74.53,67 74.53,66.08 74.53,66.05 | CD4.1 69.3,61.44 69.3,62.4 | CD1.1 91.52,56.36 91.52,57.32
  Route3 0.203: v4.53,9.01 4.85,9.01
  Route3 0.305: v99.15,66.16 99.15,66.48 | v99.15,55.69 99.15,55.37
  pour Route3 (no thermals): 88.99,65.84 88.99,55.69 89.62,55.05 100.1,55.05 100.1,79.5 39.77,79.5 39.77,69.97 0.72,30.92 0.72,2.34 1.67,1.39 50.89,1.39 53.43,3.93 53.43,6.16 52.48,7.11 8.02,7.11 6.76,8.38 6.76,10.6 8.02,11.87 8.02,28.38 37.87,58.23 67.72,58.23 69.3,59.81 70.25,59.81 70.57,60.13 70.57,62.03 71.53,62.99 74.7,62.99 76.29,64.58 76.29,68.07 77.24,69.02 80.73,69.02 81.69,68.07 81.69,66.16 82,65.84
IR
  Top 0.203: U1.52 73.37,60.06 70.41,63.03 | 70.41,63.03 | JP7.2 43.9,69.5 49.46,63.94 69.5,63.94 70.41,63.03
L1  (via drill 0.6)
  Top 0.254: 82.95,30.6 R49.1 | 82.95,30.6 83.06,30.5 C37.2 81.37,29.02 80.73,28.38 80.73,23.94 81.37,23.3 U$39.1 | U$39.1 82.95,23.3 | U$39.1 R52.2 | 82.95,30.6 81.05,30.6 v80.73,30.29 | U5.2 80.35,36.57 v80.73,36.95
  Bottom 0.254: v80.73,30.29 v80.73,36.95
L1-1
  Top 0.203: U1.73 78.53,51.94 76.91,50.33 74.22,50.33 73.11,49.23 73.11,46.8 | 73.11,46.8 72.95,46.8 | 72,43.94 72,46.8 72.22,47.01 C10.1 73.11,46.8
  Top 0.254: C33.- 71.84,40.45 72,40.6 72,43.94
L1-2
  Top 0.203: U1.72 78.13,52.18 76.76,50.81 73.9,50.81 71.24,48.14 70.97,48.14 70.57,47.75 70.57,47.11 70.52,47.11 C9.1 | C9.1 71.31,47.01 71.53,46.8 71.53,43.94 | C9.1 70.41,46.95 | C9.1 | C9.1 70.41,47.32
  Top 0.254: 71.53,43.94 71.53,43.3 70.57,42.35 68.35,42.35 67.08,41.08 C32.-
L2
  Top 0.254: 61.05,22.03 C29.1 61.1,23.56 61.05,23.62 | 61.05,23.62 R21.2 | 61.05,23.62 60.89,23.78 IC1.9 60.89,25.68 | U2.2 60.19,28.13 60.89,27.43 60.89,25.68 | 60.89,25.68
  Top 0.406: R20.1 61.05,20.12 61.1,20.18 C29.1
L2-1
  Top 0.203: U1.68 76.53,53.12 76.12,52.71 71.99,52.71 | 71.99,52.71 72.95,52.71 | 71.99,52.71 69.93,50.65 66.49,50.65 65.17,49.34 63.27,49.34 62.32,48.38 C5.1 62.32,46.8
  Top 0.254: 62.32,46.48 62.32,46.8 61.37,46.8 61.05,46.48 61.05,42.98 60.41,42.35 57.55,42.35 56.6,41.4 56.6,41.08 56.28,40.76 56.39,40.66 C12.-
L2-2
  Top 0.203: U1.67 75.64,53.66 75.17,53.19 71.68,53.19 69.61,51.12 66.01,51.12 64.86,49.97 62.16,49.97 59.94,47.75 59.94,46.8 | 59.94,46.8 | 59.94,46.8 C25.1
  Top 0.254: 59.94,46.8 59.14,46.8 58.19,45.84 58.19,44.89 56.92,43.62 52.79,43.62 51.52,42.35 51.52,41.08 51.68,40.92 C13.-
L11
  Top 0.254: R61.2 82.95,33.14 82.64,32.83 82,32.83 81.69,32.51 81.05,32.51 80.96,32.59 U5.12
L12
  Top 0.254: 80.35,32.58 U5.11 80.35,31.94 80.73,31.55 81.69,31.55 82,31.87 R58.2 83.27,31.87
L21  (via drill 0.6)
  Top 0.254: R29.2 v55.02,24.89 | U2.12 51.77,27.36 51.05,26.63 v50.57,26.63
  Bottom 0.254: v55.02,24.89 54.86,24.89 52.79,26.95 50.89,26.95 v50.57,26.63
L22  (via drill 0.6)
  Top 0.254: U2.11 50.95,28.13 v50.57,27.74 | R32.2 56.23,26.1 56.13,26 55.97,26.16 v55.02,26.16
  Bottom 0.254: v50.57,27.74 53.43,27.74 v55.02,26.16
L222
  Top 0.254: U$39.4 83.91,27.11 84.86,28.06 84.86,29.02 | R61.1 84.76,31.98 84.86,31.87 R58.1 84.76,30.7 84.86,30.6 | 84.86,29.02 C37.1 | 84.86,29.02 84.76,29.12 R49.2 84.86,30.6 | R24.1 85.28,31.02 84.86,30.6
LEFT
  Top 0.254: U1.83 82.53,45 83.75,43.78 83.75,43.3 R13.2 84.33,43.2 84.7,42.83 84.7,39.65 93.91,30.44 94.86,30.44 95.34,29.97 95.34,29.33 95.5,29.17 95.39,29.07 R15.2
MIC2N  (via drill 0.6)
  Top 0.203: U1.71 77.73,52.41 76.6,51.28 73.9,51.28 73.42,51.28 70.84,48.7 68.98,48.7 v68.83,48.54 68.51,48.22 C8.1 | C8.1 68.51,46.8 | C8.1 | C69.1 59.46,51.56 60.41,50.61 60.89,50.61 v61.05,50.45
  Bottom 0.203: v61.05,50.45 | v61.05,50.45 61.84,49.65 67.72,49.65 v68.83,48.54
MIC2P  (via drill 0.6)
  Top 0.203: U1.70 77.33,52.65 76.44,51.76 72.95,51.76 | 72.95,51.76 73.26,51.76 | 72.95,51.76 70.52,49.34 67.72,49.34 67.24,48.86 v67.08,48.7 66.6,48.22 C7.1 | C7.1 | C68.1 59.78,49.97 v60.09,49.65
  Bottom 0.203: v60.09,49.65 60.73,49.02 66.76,49.02 v67.08,48.7
MISO0  (via drill 0.6)
  Top 0.203: U1.29 82.13,69.51 82.79,70.17 85.33,72.72 85.96,72.71 86.01,72.71 86.45,73.15 86.45,74.73 87.4,75.69 U4.2 92.96,75.69 v93.91,76.64
  Bottom 0.203: JP8.4 107.72,76.96 106.45,75.69 99.78,75.69 98.83,76.64 v93.91,76.64
MOSI0  (via drill 0.6)
  Top 0.203: U1.30 81.73,70.07 85.5,73.83 v85.5,74.58 | 96.29,73.15 U4.5 | v96.29,71.88 96.29,73.15 | 96.29,73.15 100.1,73.15 101.37,74.42 109.31,74.42 110.26,75.37 JP8.5
  Bottom 0.203: v96.29,71.88 95.34,70.92 94.38,70.92 89.62,75.69 87.4,75.69 86.45,74.73 85.65,74.73 v85.5,74.58
MUTE
  Top 0.203: U1.20 86.27,62.06 91.04,66.84 91.84,66.84 94.81,69.81 99.62,69.81 100.1,69.34 100.73,69.34 R96.2 102.22,69.23 102.32,69.34 R38.1
N$1
  Top 0.203: C14.1 77.56,44.26 | C14.1 | L1.2 77.56,46.02 C14.1
N$2  (via drill 0.6)
  Top 0.254: 77.88,19.49 78.23,19.85 C27.+ 78.23,20.16 78.19,20.12 76.92,20.12 75.65,18.86 71.21,18.86 v70.89,18.54 | v57.87,20.12 R20.2
  Top 0.406: v57.87,20.12
  Bottom 0.254: v57.87,20.12 61.68,20.12 62.32,19.49 69.94,19.49 v70.89,18.54
N$3
  Top 0.305: R3.1 55.71,58.17 55.65,58.23 55.57,58.15 CP1.2
N$4
  Top 0.254: C26.+ 72.48,20.44 71.53,19.49 63.59,19.49 62.85,20.23 R19.2
N$6
  Top 0.254: C29.2 59.4,23.56 59.46,23.62 R21.1 R33.1 | R33.1 57.87,23.62 | R33.1 57.93,24.83 57.87,24.89 R29.1 57.93,26.1 57.87,26.16 R32.1 59.62,26.16 IC1.8
N$7
  Top 0.254: C28.2 59.4,33.2 59.46,33.14 R31.1 R34.1 | R34.1 57.87,33.14 | R34.1 57.93,31.93 57.87,31.87 R30.1 57.93,30.66 57.87,30.6 R22.1 59.78,30.6 59.62,30.76 IC1.7
N$8
  Top 0.254: 98.19,12.83 98.19,12.82 | 98.19,12.83 X4.2 | 98.19,12.83 97.56,13.46 82.95,13.46 82.42,13.99 R25.2 82.42,16.73 82.64,16.95 C66.-
N$9
  Top 0.254: X4.3 100.3,15.36 96.92,15.36 96.29,14.73 R26.2 87.3,17.05 87.08,17.27 C11.-
N$11
  Top 0.254: 73.43,32.83 73.53,32.72 R23.2 73.75,32.83 73.11,32.83 70.25,35.68 70.25,36.63 69.83,37.06 C32.+
N$12
  Top 0.203: T2.1 102.32,65.53 R38.2
N$13
  Top 0.254: U8.1 70.57,22.98 70.47,23.09 R97.1 71.68,25.05 71.84,24.89 71.94,24.99 R98.2
N$14  (via drill 0.6)
  Top 0.254: C33.+ 71.84,35.68 73.11,34.41 v73.75,34.41 | R24.2 87.5,32.72 v88.03,32.19
  Bottom 0.254: v88.03,32.19 88.03,30.92 86.13,29.02 77.56,29.02 73.75,32.83 v73.75,34.41
N$15  (via drill 0.6)
  Top 0.203: v101.37,50.29 R101.2 | v75.02,24.89 75.34,24.57 U$39.7
  Bottom 0.203: v101.37,50.29 99.47,50.29 98.83,49.65 98.83,47.75 92.16,41.08 92.16,38.86 90.89,37.59 90.89,29.65 87.08,25.84 75.97,25.84 v75.02,24.89
N$16
  Top 0.203: U3.3 146.48,20.47 146.45,20.44 146.43,20.47 U3.2
  Top 0.254: U3.2 145.88,19.23 145.5,18.86 145.5,16.95 R37.1 145.4,15.46 145.5,15.36 145.4,15.26 R95.1 143.7,15.26 143.6,15.36 R35.2
N$17
  Top 0.254: CON1.WR 75.7,11.5 73.75,13.46 73.75,14.41 73.85,14.51 R27.2 73.85,17.16 73.78,17.24 | 73.78,17.24 73.75,17.27 | C26.- 73.78,17.24
N$18
  Top 0.254: C19.1 83.81,40.02 83.91,40.13 83.75,40.29 R13.1
N$19
  Top 0.254: CON1.RR 81.72,10.25 78.83,13.14 78.83,14.73 R28.2 78.72,16.42 78.19,16.95 78.23,16.99 C27.-
N$20
  Top 0.254: R33.2 56.23,23.56 55.02,22.35 52.16,22.35 48.98,25.52 48.98,31.87 51.84,34.73 51.84,36.63 51.68,36.79 C13.+
N$21
  Top 0.254: C18.1 R12.1
N$22
  Top 0.254: C17.1 R11.1
N$23
  Top 0.254: C12.+ 56.5,37.06 56.86,36.69 56.28,36.32 56.23,36.26 R34.2
N$24
  Top 0.203: MIC.1 53.11,51.88 53.43,51.56 R66.1 54.91,51.66 55.02,51.56 C72.2 56.55,51.61 56.6,51.56 C69.2
N$26
  Top 0.203: C68.2 56.6,49.97 56.55,49.91 C72.1 55.02,49.97 54.91,49.87 R65.2 53.43,49.81 52.16,49.81 51.68,49.34 MIC.2
N$27
  Top 0.203: R65.1 53.43,46.16 53.33,46.26 C70.2 55.17,46.32 | 55.17,46.32 | 55.17,46.32 C71.1 | R64.2 55.12,46.38 55.17,46.32
N$28  (via drill 0.6)
  Top 0.203: LED8.A 26.98,8.79 v26.76,9.01 | v23.9,19.17 23.9,19.81 24.38,20.28 24.38,20.92 24.43,20.98 R78.2
  Bottom 0.203: v26.76,9.01 26.76,16.32 v23.9,19.17
N$29  (via drill 0.6)
  Top 0.254: U3.5 147.83,18.64 v147.72,18.54 | C21.+ 164.22,6.48 164.24,6.47 v164.24,5.2
  Bottom 0.254: v147.72,18.54 147.72,17.9 149.95,15.68 156.62,15.68 157.57,14.73 157.57,12.82 158.52,11.87 160.74,11.87 163.6,9.01 163.6,5.52 163.92,5.2 v164.24,5.2
N$30
  Top 0.254: IC1.2 65.97,32.67 66.44,33.14 67.4,33.14 | 67.4,33.14 R6.1 | 67.4,33.14 R7.1
N$31  (via drill 0.6)
  Top 0.254: U3.4 147.18,19.26 v146.45,18.54 | 164.24,2.34 C36.+ v161.38,2.34
  Bottom 0.254: v146.45,18.54 146.45,17.27 148.68,15.05 155.03,15.05 155.66,14.41 155.66,12.5 157.25,10.92 159.79,10.92 161.38,9.33 v161.38,2.34
N$32  (via drill 0.6)
  Top 0.203: T2.3 101.53,62.19 v102.32,61.4 | C16.1 152.49,12.5 151.53,12.5 150.9,13.14 v150.9,13.77 150.9,15.36 152.38,16.85 R36.1 | R36.1 152.49,16.63 | R36.1 152.49,16.95
  Top 0.254: U3.12 152.38,19.28 152.65,19.01 152.65,17.11 152.49,16.95
  Bottom 0.203: v102.32,61.4 101.37,60.45 101.37,55.69 108.67,48.38 108.67,30.92 112.8,26.79 135.66,26.79 141.38,21.08 143.92,21.08 144.87,20.12 144.87,17.59 148.36,14.09 150.58,14.09 v150.9,13.77
N$33
  Top 0.254: 67.4,30.29 67.24,30.44 IC1.1 67.24,31.4 67.3,31.45 R10.1 68.98,31.4 70.25,32.67 70.25,32.83 70.47,33.04 R7.2
N$34  (via drill 0.6)
  Top 0.203: R67.1 55.12,53.25 55.02,53.14 54.8,53.36 R66.2 51.94,53.36 v51.84,53.46 | C70.1 51.62,46.26 51.52,46.16 v49.94,46.16
  Bottom 0.203: v51.84,53.46 52.48,52.83 52.48,48.7 v49.94,46.16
